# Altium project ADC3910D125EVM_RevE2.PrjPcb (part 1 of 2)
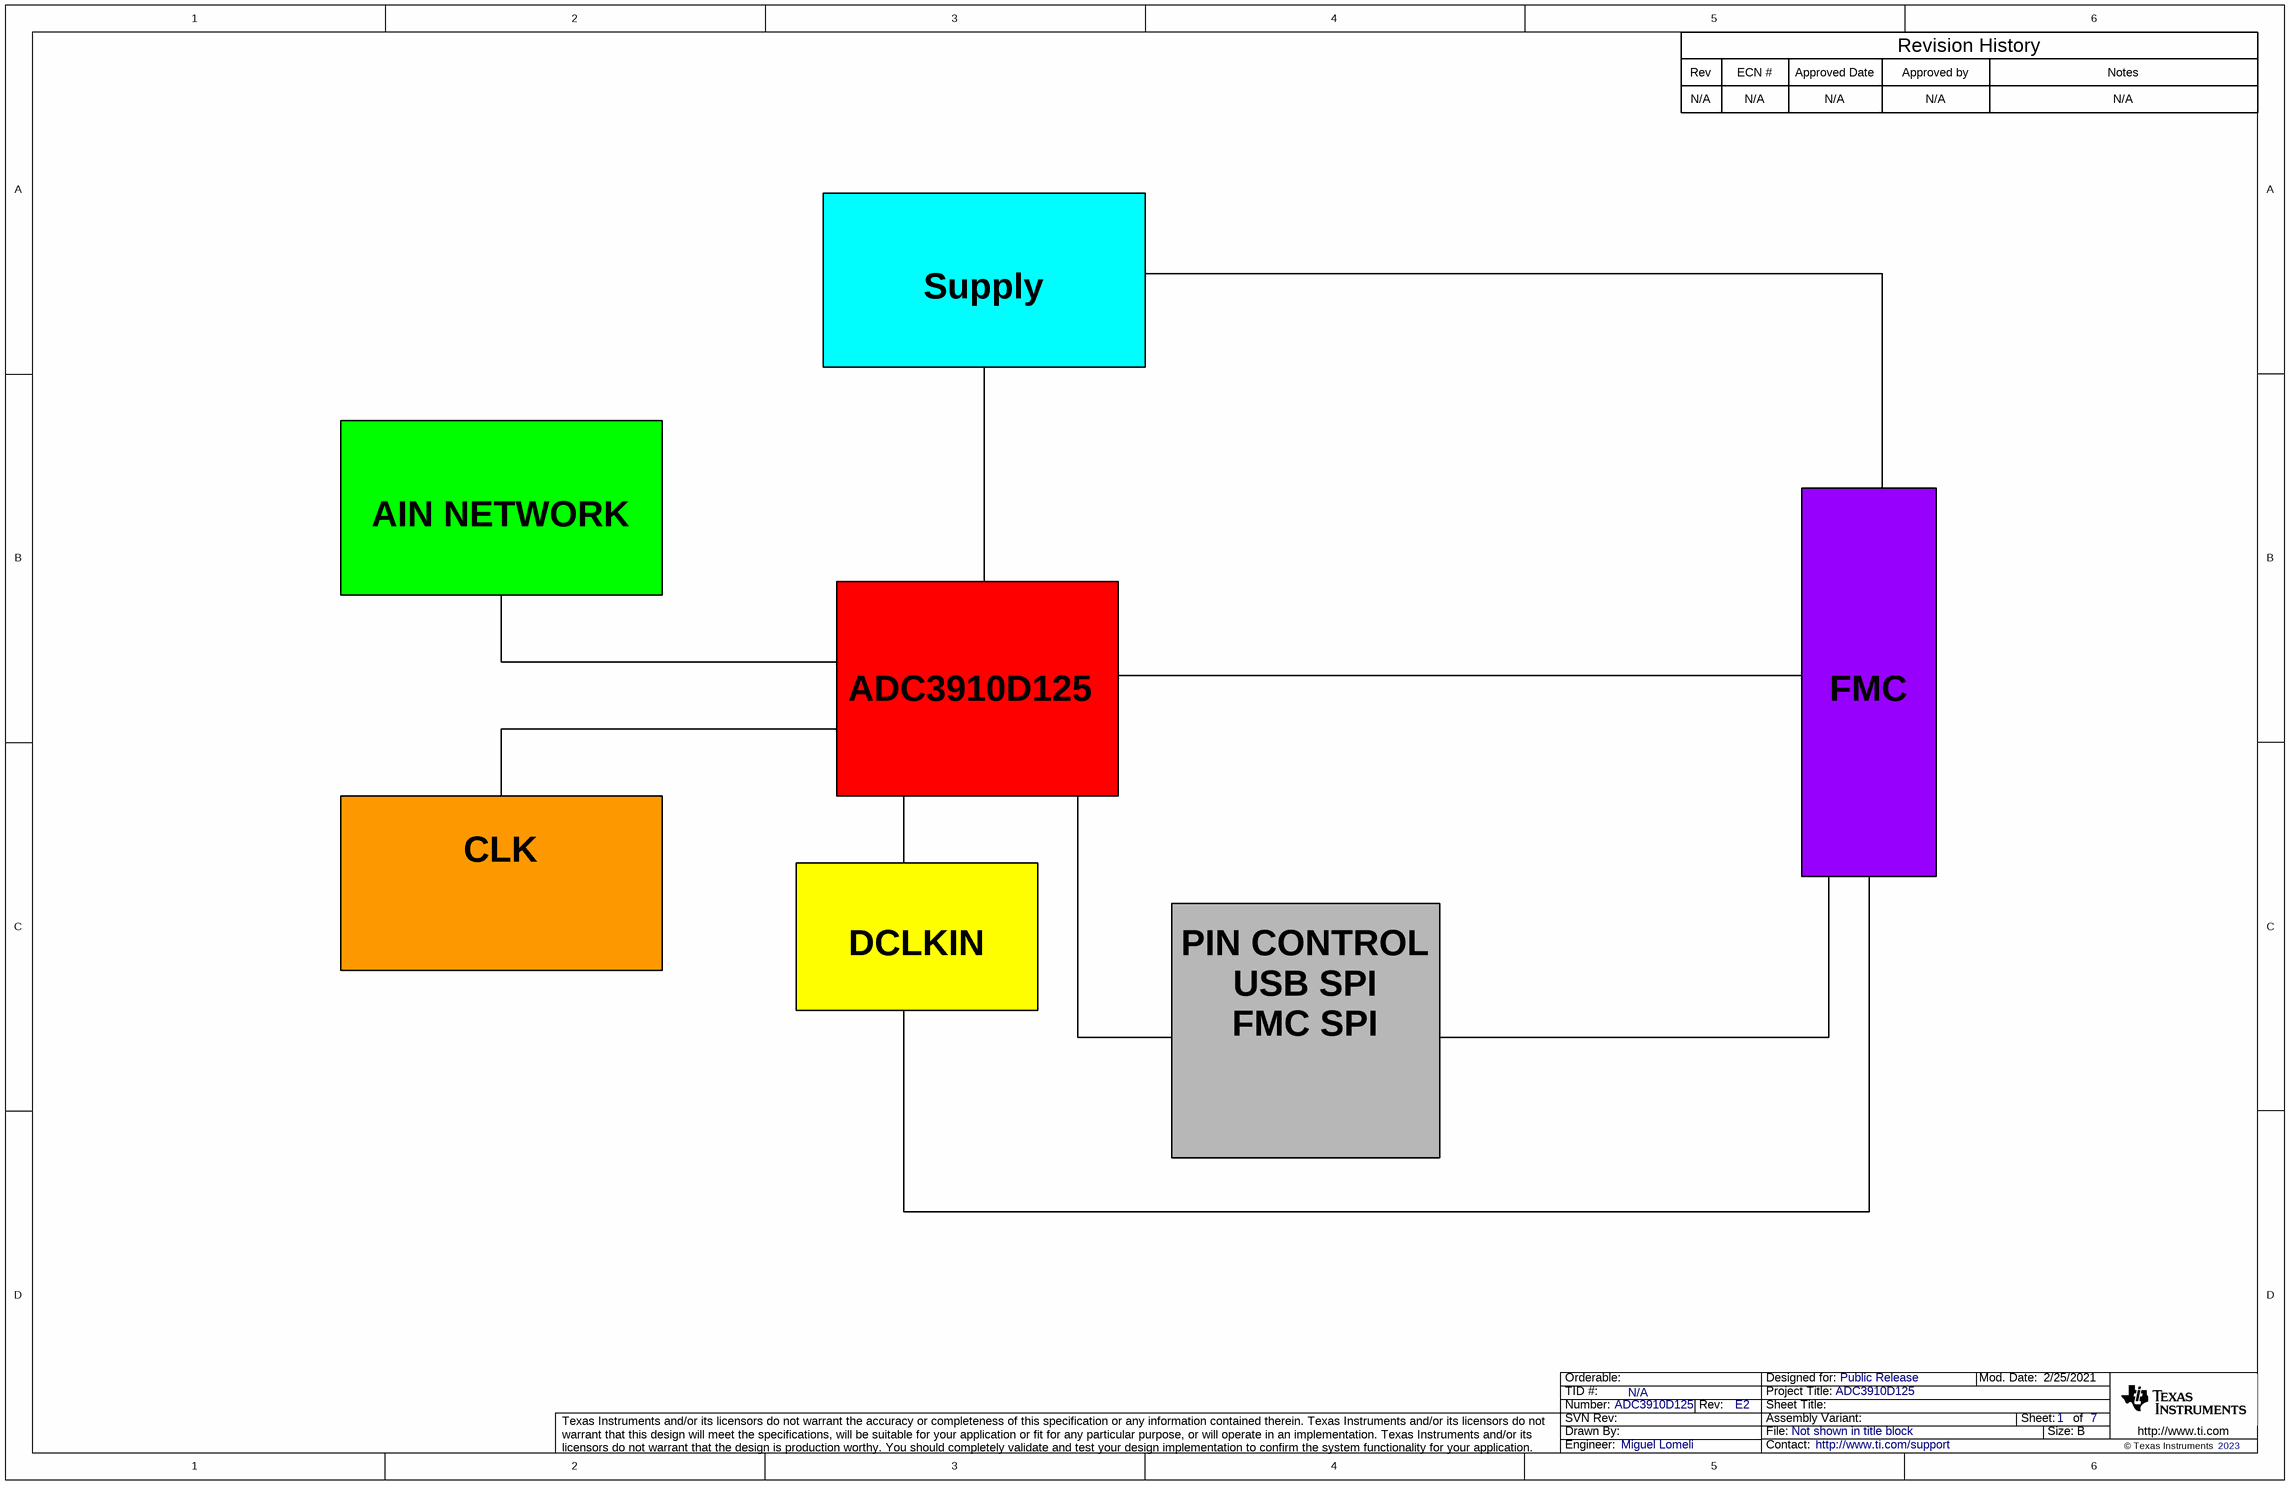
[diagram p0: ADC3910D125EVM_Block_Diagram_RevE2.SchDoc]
CopyrightYear: 2023; PCB_Layout: Miguel Lomeli; PCB_Rev: E2; PRJ_Customer: Public Release; PRJ_Engineer: Miguel Lomeli; PRJ_Number: ADC3910D125; PRJ_Title: ADC3910D125; SCH_Rev: E2; TechSupport: http://www.ti.com/support; TID: N/A
7 sheets, 322 parts. Net scope: flat (ports and power ports of the same name join across sheets).
Board file: ADC3910D125EVM_RevE2.PcbDoc
Sheets:
  ADC3910D125EVM_Block_Diagram_RevE2.SchDoc
  ADC3910D125EVM_Power_RevE2.SchDoc
  ADC3910D125EVM_AIN_CLK_RevE2.SchDoc
  ADC3910D125EVM_DUT_RevE2.SchDoc
  ADC3910D125EVM_USB_Control_RevE2.SchDoc
  ADC3910D125EVM_TSW1418_Header_RevE2.SchDoc
  ADC3910D125EVM_Hardware_RevE2.SchDoc

## Sheet ADC3910D125EVM_Block_Diagram_RevE2.SchDoc
size 431 x 279 mm; Date: Not shown in title block; ApprovedBy: Not shown in title block; CheckedBy: Not shown in title block; Author: Not shown in title block; CompanyName: Not shown in title block; Engineer: Not shown in title block; Organization: Not shown in title block; Address1: Not shown in title block; Address2: Not shown in title block; Address3: Not shown in title block; Address4: Not shown in title block; DocumentNumber: 1; Revision: Use project parameter SCH_Rev; SheetNumber: 1; SheetTotal: 7; PageSetup: Record=PageOptions¦CenterHorizontal=True¦CenterVertical=True¦PrintScale=1.00¦XCorrection=1.00¦YCorrection=1.00¦PrintKind=0¦BorderSize=5000000¦LeftOffset=0¦BottomOffset=0¦Orientation=2¦PaperLength=1000¦PaperWidth=1000¦Scale=100¦PaperSource=15¦PrintQuality=600¦MediaType=1¦DitherType=10¦PaperKind=Letter¦PrintScaleMode=1

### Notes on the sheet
- Rev
- N/A
- ECN #
- Approved Date
- Approved by
- Revision History
- Notes
- Supply
- AIN NETWORK
- ADC3910D125
- FMC
- CLK
- DCLKIN
- PIN CONTROL
- USB SPI
- FMC SPI

## Sheet ADC3910D125EVM_Power_RevE2.SchDoc: Blank Sheet
size 431 x 279 mm; Date: Not shown in title block; ApprovedBy: Not shown in title block; CheckedBy: Not shown in title block; Author: Not shown in title block; CompanyName: Not shown in title block; Engineer: Not shown in title block; Organization: Not shown in title block; Address1: Not shown in title block; Address2: Not shown in title block; Address3: Not shown in title block; Address4: Not shown in title block; DocumentNumber: 5; Revision: Use project parameter SCH_Rev; SheetNumber: 2; SheetTotal: 7; PageSetup: Record=PageOptions¦CenterHorizontal=True¦CenterVertical=True¦PrintScale=1.00¦XCorrection=1.00¦YCorrection=1.00¦PrintKind=0¦BorderSize=5000000¦LeftOffset=0¦BottomOffset=0¦Orientation=2¦PaperLength=1000¦PaperWidth=1000¦Scale=100¦PaperSource=15¦PrintQuality=600¦MediaType=1¦DitherType=10¦PaperKind=Letter¦PrintScaleMode=1
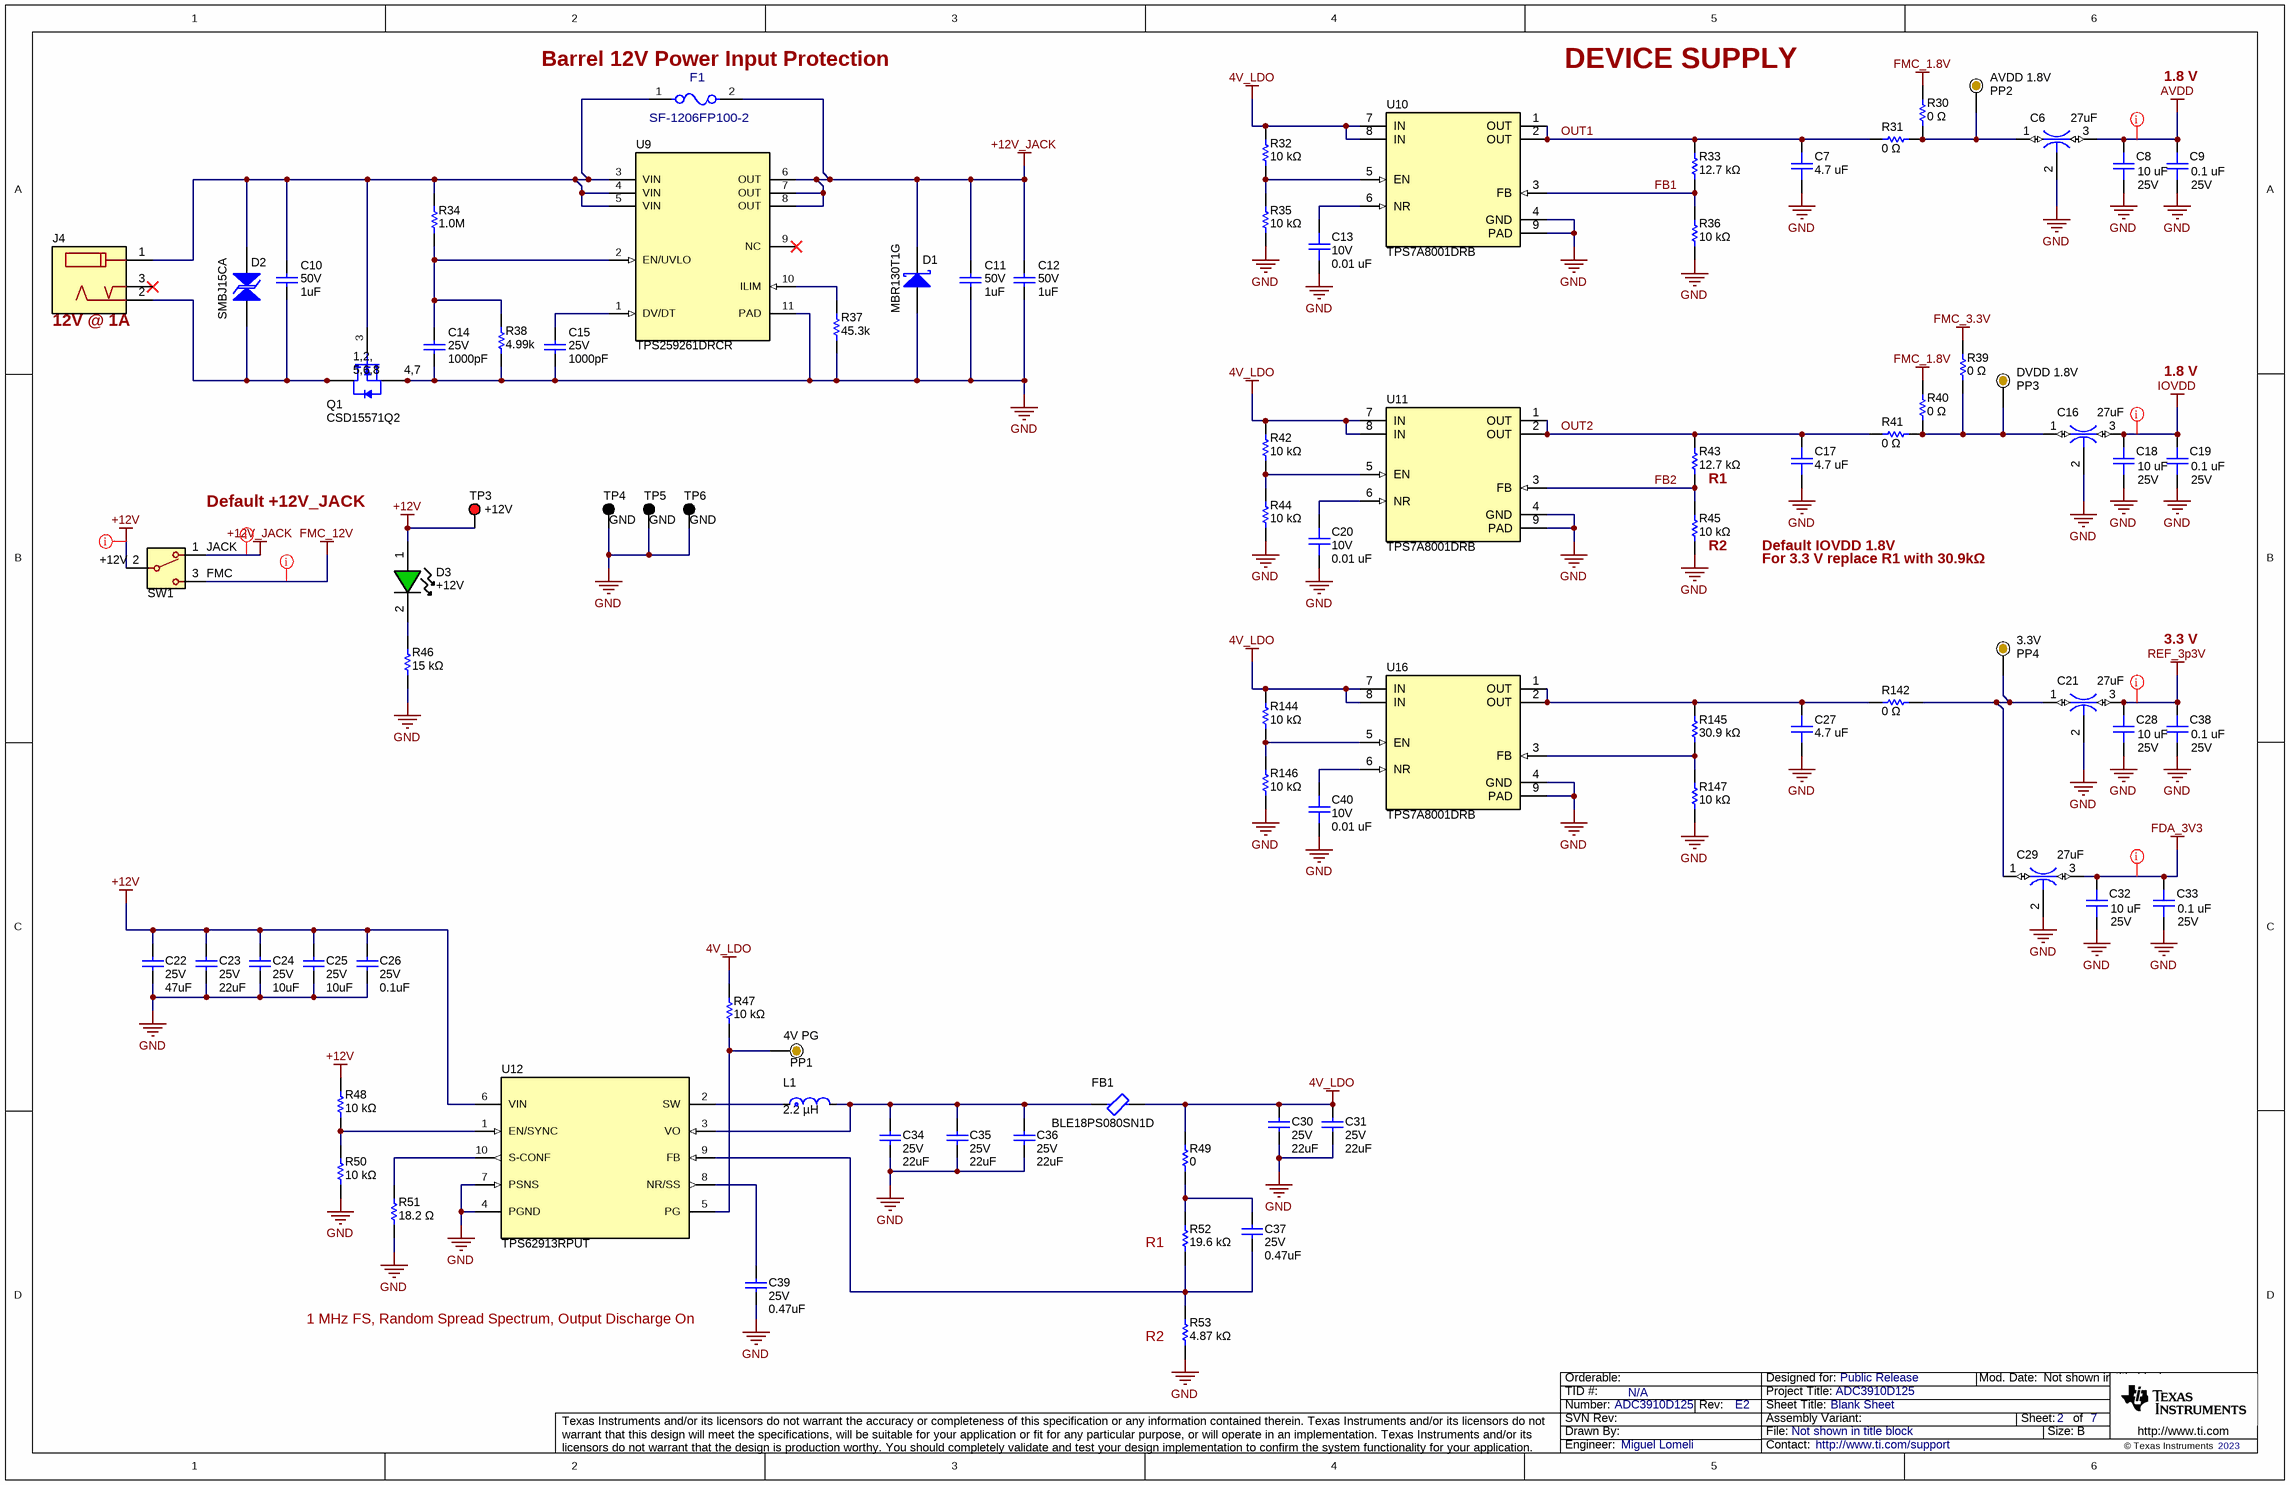
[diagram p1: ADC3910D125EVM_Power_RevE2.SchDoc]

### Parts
C6  value 27uF  [NFM31PC]  (hidden comment: NFM31PC276B0J3L)
C7  value 4.7 uF  [0402L_cap]  (hidden comment: C1005X5R1A475K050BC)
C8  value 10 uF  Voltage - Rated: 25V  [0603L_cap]  (hidden comment: GRM188R61E106KA73J)
C9  value 0.1 uF  Voltage - Rated: 25V  [0402L_cap]  (hidden comment: GRT155R71E104KE01J)
C10  VDC_V: 50V  ValueDisplayed: 1uF  [0805_HV]  (hidden comment: C0805C105K5RACTU)
C11  VDC_V: 50V  ValueDisplayed: 1uF  [0805_HV]  (hidden comment: C0805C105K5RACTU)
C12  VDC_V: 50V  ValueDisplayed: 1uF  [0805_HV]  (hidden comment: C0805C105K5RACTU)
C13  value 0.01 uF  Voltage - Rated: 10V  [0402L_cap]  (hidden comment: 0402ZC103JAT2A)
C14  VDC_V: 25V  ValueDisplayed: 1000pF  [0201_033]  (hidden comment: GRM033R71E102KA01D)
C15  VDC_V: 25V  ValueDisplayed: 1000pF  [0201_033]  (hidden comment: GRM033R71E102KA01D)
C16  value 27uF  [NFM31PC]  (hidden comment: NFM31PC276B0J3L)
C17  value 4.7 uF  [0402L_cap]  (hidden comment: C1005X5R1A475K050BC)
C18  value 10 uF  Voltage - Rated: 25V  [0603L_cap]  (hidden comment: GRM188R61E106KA73J)
C19  value 0.1 uF  Voltage - Rated: 25V  [0402L_cap]  (hidden comment: GRT155R71E104KE01J)
C20  value 0.01 uF  Voltage - Rated: 10V  [0402L_cap]  (hidden comment: 0402ZC103JAT2A)
C21  value 27uF  [NFM31PC]  (hidden comment: NFM31PC276B0J3L)
C22  VDC_V: 25V  ValueDisplayed: 47uF  [1206_190L]  (hidden comment: C3216X5R1E476M160AC)
C23  VDC_V: 25V  ValueDisplayed: 22uF  [0805L]  (hidden comment: GRM21BR61E226ME44L)
C24  VDC_V: 25V  ValueDisplayed: 10uF  [0603L]  (hidden comment: C1608X5R1E106M080AC)
C25  VDC_V: 25V  ValueDisplayed: 10uF  [0603L]  (hidden comment: C1608X5R1E106M080AC)
C26  VDC_V: 25V  ValueDisplayed: 0.1uF  [0201_033]  (hidden comment: GRM033C81E104KE14D)
C27  value 4.7 uF  [0402L_cap]  (hidden comment: C1005X5R1A475K050BC)
C28  value 10 uF  Voltage - Rated: 25V  [0603L_cap]  (hidden comment: GRM188R61E106KA73J)
C29  value 27uF  [NFM31PC]  (hidden comment: NFM31PC276B0J3L)
C30  VDC_V: 25V  ValueDisplayed: 22uF  [0805L]  (hidden comment: GRM21BR61E226ME44L)
C31  VDC_V: 25V  ValueDisplayed: 22uF  [0805L]  (hidden comment: GRM21BR61E226ME44L)
C32  value 10 uF  Voltage - Rated: 25V  [0603L_cap]  (hidden comment: GRM188R61E106KA73J)
C33  value 0.1 uF  Voltage - Rated: 25V  [0402L_cap]  (hidden comment: GRT155R71E104KE01J)
C34  VDC_V: 25V  ValueDisplayed: 22uF  [0805L]  (hidden comment: GRM21BR61E226ME44L)
C35  VDC_V: 25V  ValueDisplayed: 22uF  [0805L]  (hidden comment: GRM21BR61E226ME44L)
C36  VDC_V: 25V  ValueDisplayed: 22uF  [0805L]  (hidden comment: GRM21BR61E226ME44L)
C37  VDC_V: 25V  ValueDisplayed: 0.47uF  [0402L]  (hidden comment: GRM155R61E474KE01D)
C38  value 0.1 uF  Voltage - Rated: 25V  [0402L_cap]  (hidden comment: GRT155R71E104KE01J)
C39  VDC_V: 25V  ValueDisplayed: 0.47uF  [0402L]  (hidden comment: GRM155R61E474KE01D)
C40  value 0.01 uF  Voltage - Rated: 10V  [0402L_cap]  (hidden comment: 0402ZC103JAT2A)
D1  MBR130T1G  [SOD-123]
D2  SMBJ15CA  [SMB-Bi]
D3  Text1: +12V  [LED_LTST-C190-Green]  (hidden comment: LTST-C191TGKT)
F1  SF-1206FP100-2  [FP-SF-1206FP100-2_1206-MFG]
FB1  BLE18PS080SN1D  [0603L]
J4  Text1: 12V @ 1A  [RAPC722X]  (hidden comment: RAPC722X)
L1  value 2.2 µH  [XGL5030]  (hidden comment: XGL5030-222MEC)
PP1  Text1: 4V PG  [ProbePoint_TH_40mil]  (hidden comment: Probe Point)  (no BOM)
PP2  Text1: AVDD 1.8V  [ProbePoint_TH_40mil]  (hidden comment: Probe Point)  (no BOM)
PP3  Text1: DVDD 1.8V  [ProbePoint_TH_40mil]  (hidden comment: Probe Point)  (no BOM)
PP4  Text1: 3.3V  [ProbePoint_TH_40mil]  (hidden comment: Probe Point)  (no BOM)
Q1  CSD15571Q2  [DQK0006C]
R30  value 0 Ω  [0603L]  (hidden comment: ERJ-U030R00V)
R31  value 0 Ω  [0603L]  (hidden comment: ERJ-U030R00V)
R32  value 10 kΩ  [0402L]  (hidden comment: ERJ-2RKF1002X)
R33  value 12.7 kΩ  [0402L]  (hidden comment: ERJ-2RKF1272X)
R34  ValueDisplayed: 1.0M  [0201]  (hidden comment: RC0201JR-071ML)
R35  value 10 kΩ  [0402L]  (hidden comment: ERJ-2RKF1002X)
R36  value 10 kΩ  [0402L]  (hidden comment: ERJ-2RKF1002X)
R37  ValueDisplayed: 45.3k  [0201]  (hidden comment: RC0201FR-7D45K3L)
R38  ValueDisplayed: 4.99k  [0201]  (hidden comment: RC0201FS-7D4K99L)
R39  value 0 Ω  [0603L]  (hidden comment: ERJ-U030R00V)
R40  value 0 Ω  [0603L]  (hidden comment: ERJ-U030R00V)
R41  value 0 Ω  [0603L]  (hidden comment: ERJ-U030R00V)
R42  value 10 kΩ  [0402L]  (hidden comment: ERJ-2RKF1002X)
R43  value 12.7 kΩ  [0402L]  (hidden comment: ERJ-2RKF1272X)
R44  value 10 kΩ  [0402L]  (hidden comment: ERJ-2RKF1002X)
R45  value 10 kΩ  [0402L]  (hidden comment: ERJ-2RKF1002X)
R46  value 15 kΩ  [0603L]  (hidden comment: ERJ-UP3F1502V)
R47  value 10 kΩ  [0402L]  (hidden comment: ERJ-2RKF1002X)
R48  value 10 kΩ  [0402L]  (hidden comment: ERJ-2RKF1002X)
R49  ValueDisplayed: 0  [0402L]  (hidden comment: ERJ-2GE0R00X)
R50  value 10 kΩ  [0402L]  (hidden comment: ERJ-2RKF1002X)
R51  value 18.2 Ω  [0402L]  (hidden comment: ERJ-2RKF18R2X)
R52  value 19.6 kΩ  [0402L]  (hidden comment: ERJ-2RKF1962X)
R53  value 4.87 kΩ  [0402L]  (hidden comment: ERJ-2RKF4871X)
R142  value 0 Ω  [0603L]  (hidden comment: ERJ-U030R00V)
R144  value 10 kΩ  [0402L]  (hidden comment: ERJ-2RKF1002X)
R145  value 30.9 kΩ  [0402L]  (hidden comment: ERJ-2RKF3092X)
R146  value 10 kΩ  [0402L]  (hidden comment: ERJ-2RKF1002X)
R147  value 10 kΩ  [0402L]  (hidden comment: ERJ-2RKF1002X)
SW1  Text1: JACK  Text2: +12V  Text3: FMC  [FP-1101M2S3CGE2_SIP3-MFG]  (hidden comment: 1101M2S3CGE2)
TP3  Text1: +12V  [Keystone5000]  (hidden comment: 5000)
TP4  Text1: GND  [Keystone5011]  (hidden comment: 5011)
TP5  Text1: GND  [Keystone5011]  (hidden comment: 5011)
TP6  Text1: GND  [Keystone5011]  (hidden comment: 5011)
U9  TPS259261DRCR  [DRC0010J]
U10  TPS7A8001DRB  [DRB0008A]
U11  TPS7A8001DRB  [DRB0008A]
U12  TPS62913RPUT  [RPU0010A]
U16  TPS7A8001DRB  [DRB0008A]

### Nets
4V_LDO: C30.1 C31.1 FB1.2 R32.2 R42.2 R47.2 R49.2 R144.2 U10.7(IN) U10.8(IN) U11.7(IN) U11.8(IN) U16.7(IN) U16.8(IN)
+12V: C22.1 C23.1 C24.1 C25.1 C26.1 D3.1(A) R48.2 SW1.2(COMM) TP3.1 U12.6(VIN)
+12V_JACK: C11.1 C12.1 D1.1(K) F1.2 SW1.1 U9.6(OUT) U9.7(OUT) U9.8(OUT)
AVDD: C6.3 C8.2 C9.2
FDA_3V3: C29.3 C32.2 C33.2
FMC_1.8V: R30.2 R40.1
FMC_3.3V: R39.2
FMC_12V: SW1.3
GND: C6.2 C7.1 C8.1 C9.1 C11.2 C12.2 C13.1 C14.2 C15.2 C16.2 C17.1 C18.1 C19.1 C20.1 C21.2 C22.2 C23.2 C24.2 C25.2 C26.2 C27.1 C28.1 C29.2 C30.2 C31.2 C32.1 C33.1 C34.2 C35.2 C36.2 C38.1 C39.2 C40.1 D1.2(A) Q1.4(S) Q1.7(S) R35.1 R36.1 R37.1 R38.2 R44.1 R45.1 R46.1 R50.1 R51.1 R53.1 R146.1 R147.1 TP4.1 TP5.1 TP6.1 U9.11(PAD) U10.4(GND) U10.9(PAD) U11.4(GND) U11.9(PAD) U12.4(PGND) U12.7(PSNS) U16.4(GND) U16.9(PAD)
IOVDD: C16.3 C18.2 C19.2
REF_3p3V: C21.3 C28.2 C38.2
FB1: R33.1 R36.2 U10.3(FB)
FB2: R43.1 R45.2 U11.3(FB)
OUT1: C7.2 R31.2 R33.2 U10.1(OUT) U10.2(OUT)
OUT2: C17.2 R41.2 R43.2 U11.1(OUT) U11.2(OUT)
NetC6_1: C6.1 PP2.1 R30.1 R31.1
NetC10_1: C10.1 D2.2 F1.1 J4.1 Q1.3(G) R34.2 U9.3(VIN) U9.4(VIN) U9.5(VIN)
NetC10_2: C10.2 D2.1 J4.2 Q1.1(D) Q1.2(D) Q1.5(D) Q1.6(D) Q1.8(D)
NetC13_2: C13.2 U10.6(NR)
NetC14_1: C14.1 R34.1 R38.1 U9.2(EN/UVLO)
NetC15_1: C15.1 U9.1(DV/DT)
NetC16_1: C16.1 PP3.1 R39.1 R40.2 R41.1
NetC20_2: C20.2 U11.6(NR)
NetC21_1: C21.1 C29.1 PP4.1 R142.1
NetC27_2: C27.2 R142.2 R145.2 U16.1(OUT) U16.2(OUT)
NetC34_1: C34.1 C35.1 C36.1 FB1.1 L1.2 U12.3(VO)
NetC37_1: C37.1 R49.1 R52.2
NetC37_2: C37.2 R52.1 R53.2 U12.9(FB)
NetC39_1: C39.1 U12.8(NR/SS)
NetC40_2: C40.2 U16.6(NR)
NetD3_2: D3.2(K) R46.2
NetL1_1: L1.1 U12.2(SW)
NetPP1_1: PP1.1 R47.1 U12.5(PG)
NetR32_1: R32.1 R35.2 U10.5(EN)
NetR37_2: R37.2 U9.10(ILIM)
NetR42_1: R42.1 R44.2 U11.5(EN)
NetR48_1: R48.1 R50.2 U12.1(EN/SYNC)
NetR51_2: R51.2 U12.10(S-CONF)
NetR144_1: R144.1 R146.2 U16.5(EN)
NetR145_1: R145.1 R147.2 U16.3(FB)

Not connected (* = marked no-connect by the designer): J4 3*; U9 9(NC)*

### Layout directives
net class Power: +12V, +12V_JACK, AVDD, FDA_3V3, FMC_12V, IOVDD, REF_3p3V

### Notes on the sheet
- (near F1) Barrel 12V Power Input Protection
- DEVICE SUPPLY
- 1.8 V
- Default +12V_JACK
- (near R43) R1
- (near R45) R2
- Default IOVDD 1.8V
- For 3.3 V replace R1 with 30.9kΩ
- 3.3 V
- (near R52) R1
- 1 MHz FS, Random Spread Spectrum, Output Discharge On
- (near R53) R2

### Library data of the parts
C6 C16 C21 C29 = dcp00001: Feed through capactior 27uF; Manufacturer: Murata; CompType: Feed Thru Cap; Tolerance: ±20%; Voltage - Rated: 6.3V; Current: 6A; DCR: 5 mΩ; SizeX_mm: 3.2; SizeY_mm: 1.6; SizeZ_mm: 1.5
C7 C17 C27 = capcc03298: CAP CER 4.7UF 10V X5R 0402; Manufacturer: TDK Corporation; Tolerance: ±10%; SizeX_mm: 1; SizeY_mm: 0.5; SizeZ_mm: 0.65; CompType: Capacitor Ceramic
C8 C18 C28 C32 = capcc09400: CAP CER 10UF 25V X5R 0603; Manufacturer: Murata; SizeZ_mm: 1; SizeX_mm: 1.6; SizeY_mm: 0.8; CompType: Capacitor Ceramic; Tolerance: ±10%
C9 C19 C33 C38 = capcc09401: CAP CER 0.1UF 25V X7R 0402; Manufacturer: Murata; SizeZ_mm: 0.7; SizeX_mm: 1; SizeY_mm: 0.5; CompType: Capacitor Ceramic; Tolerance: ±10%
C10-C12 = CMP-0007730-2: CAP, CERM, 1 uF, 50 V, +/- 10%, X7R, 0805; Manufacturer: Kemet; TaMin_C: -55°C; Polarized: N; SizeAreaWB_mm2: 6.75; Value1: Unknown; U/M: EA; Value: 1uF; TaMax_C: 125°C; SizeZ_mm: 1.45; SizeX_mm: 2; SizeY_mm: 1.25; Cap_Case: 0805; SizeArea_mm2: 2.5; Cap_F: 1µF; AEC Category: Q200
C13 C20 C40 = capcc05563: CAP CER 10000PF 10V X7R 0402; Manufacturer: KYOCERA AVX; CompType: Capacitor Ceramic; Tolerance: ±5%; SizeX_mm: 1; SizeY_mm: 0.5; SizeZ_mm: 0.56
C14 C15 = CMP-0009764-1: CAP, CERM, 1000 pF, 25 V, +/- 10%, X7R, 0201; Manufacturer: MuRata; TaMin_C: -55°C; Polarized: N; SizeAreaWB_mm2: 2.08; Value1: Unknown; U/M: EA; Value: 1000pF; TaMax_C: 125°C; SizeZ_mm: 0.33; SizeX_mm: 0.6; SizeY_mm: 0.3; Cap_Case: 0201; SizeArea_mm2: 0.18; Cap_F: 1nF; AEC Category: Q200
C22 = CMP-0008656-2: CAP, CERM, 47 uF, 25 V, +/- 20%, X5R, 1206_190; Manufacturer: TDK; TaMin_C: -55°C; Polarized: N; SizeAreaWB_mm2: 10.92; Value1: Unknown; U/M: EA; Value: 47uF; TaMax_C: 85°C; SizeZ_mm: 1.9; SizeX_mm: 3.2; SizeY_mm: 1.6; Cap_Case: 1206; SizeArea_mm2: 5.12; Cap_F: 47µF; AEC Category: Q200
C23 C30 C31 C34-C36 = CMP-0008305-2: CAP, CERM, 22 uF, 25 V, +/- 20%, X5R, 0805; Manufacturer: MuRata; TaMin_C: -55°C; Polarized: N; SizeAreaWB_mm2: 6.75; Value1: Unknown; U/M: EA; Value: 22uF; TaMax_C: 85°C; SizeZ_mm: 1.45; SizeX_mm: 2; SizeY_mm: 1.25; Cap_Case: 0805; SizeArea_mm2: 2.5; Cap_F: 22µF; AEC Category: Q200
C24 C25 = CMP-0007007-5: CAP, CERM, 10 uF, 25 V, +/- 20%, X5R, 0603; Manufacturer: TDK; TaMin_C: -55°C; ESR_ohm: 4.639m; Polarized: N; SizeAreaWB_mm2: 4.68; Value1: 0.004639 ohm; U/M: EA; Value: 10uF; TaMax_C: 85°C; SizeZ_mm: 1; SizeX_mm: 1.6; SizeY_mm: 0.8; Cap_Case: 0603; SizeArea_mm2: 1.28; Cap_F: 10µF; IRMS_A: 2.4141A; AEC Category: Q200
C26 = CMP-0009688-3: CAP, CERM, 0.1 uF, 25 V, +/- 10%, X6S, 0201; Manufacturer: MuRata; TaMin_C: -55°C; Polarized: N; SizeAreaWB_mm2: 2.08; Value1: Unknown; U/M: EA; Value: 0.1uF; TaMax_C: 105°C; SizeZ_mm: 0.33; SizeX_mm: 0.6; SizeY_mm: 0.3; Cap_Case: 0201; SizeArea_mm2: 0.18; Cap_F: 100nF; AEC Category: Q200
C37 C39 = CMP-0064928-2: CAP, CERM, 0.47 uF, 25 V,+/- 10%, X5R, 0402; Manufacturer: MuRata; TaMin_C: -55°C; Polarized: N; SizeAreaWB_mm2: 3; Value1: Unknown; U/M: EA; Value: 0.47uF; TaMax_C: 85°C; SizeZ_mm: 0.6; SizeX_mm: 1; SizeY_mm: 0.5; Cap_Case: 0402; Cap_F: 470nF; AEC Category: Q200
D1 = CMP-0028547-2: Diode, Schottky, 30 V, 1 A, SOD-123; Manufacturer: ON Semiconductor; Io_A: 1A; Green_Lifecycle: Active; SizeAreaWB_mm2: 13.095; Vr_V: 30V; Green_REACh: Passed; TJmax_C: 125°C; Value: 30V; SizeZ_mm: 1.35; SizeX_mm: 3.85; SizeY_mm: 1.7; Vf_V: 470mV; Value2: 0.47V; SizeArea_mm2: 6.545; AEC Category: Q101; RJC_CperW: 108
D2 = CMP-0006044-3: Diode, TVS, Bi, 15 V, 24.4 Vc, SMB; Manufacturer: Fairchild Semiconductor; Value1: 600W; Value: 15V; AEC Category: Q101; Ppk: 15kW
D3 = cmp00247: LED GREEN CLEAR CHIP SMD; Manufacturer: Lite-On Inc.; Current Rating (Amps): 20mA; Voltage - Forward (Vf) (Typ): 3.2V; SizeX_mm: 1.6; SizeY_mm: 0.8; SizeZ_mm: 0.65
F1 = CMP-0095990-1: 1 A AC 63 V DC Fuse Board Mount (Cartridge Style Excluded) Surface Mount 1206 (3216 Metric); Manufacturer: Bourns; SizeZ_mm: 0.7mm; MeltingTyp: 0.062A2Sec; Fuse Speed: Fast; Res_ohm: 0.1455Ω; Fuse Interrupt Dc Current: 50A; AEC Qualified: No; Fuse Current: 1A
FB1 = dcp00379: FERRITE BEAD; Manufacturer: Murata Electronics; Current: 8A; Impedance: 8.5 Ω; DCR: 4 mΩ
J4 = cmp00022: Power Jack, mini, 2.1mm OD, R/A, TH; Manufacturer: Switchcraft
L1 = LSMT56800038: POWER INDUCTOR, SHIELDED, COMPOS; Manufacturer: COILCRAFT; Current Rating (Amps): 12.9 A; Current - Saturation (Isat): 9.4A; DC Resistance (DCR): 10.6m Ω; Inductance Frequency - Test: 1 MHz; Frequency - Self Resonant: 34MHz; SizeX_mm: 5.68; SizeY_mm: 5.48; SizeZ_mm: 3.1
PP1-PP4 = cmp00025: Probe Point that can be used in lue of a test point
Q1 = CMP-0000207-1: MOSFET, N-CH, 20 V, 10 A, DQK0006C (WSON-6); Alternate Manufacturer: None; Manufacturer: Texas Instruments; SizeZ_mm: 0.8; ChType: N; Value2: 2.5 nC; Value1: 19; VdsMax_V: 20V; SizeX_mm: 2; Value: 20V; Rdson45_ohm: 19.2; SizeArea_mm2: 4; AEC Category: Q101; IdsMax_A: 10A; SizeAreaWB_mm2: 9; U/M: EA; QgTyp_nC: 2.5
R30 R31 R39-R41 R142 = RSMD060312253: RES 0 OHM JUMPER 0603 SMD; Manufacturer: Panasonic Electronic Components; Power (Watts): 0.1W, 1/10W; Temperature Coefficient: ±200ppm/°C; SizeX_mm: 1.6; SizeY_mm: 0.8; SizeZ_mm: 0.55; CompType: Resistor SMD
R32 R35 R36 R42 R44 R45 R47 R48 R50 R144 R146 R147 = RSMD040200314: RES SMD 10K OHM 1% 1/10W 0402; Manufacturer: Panasonic Electronic Components; Power (Watts): 0.1W, 1/10W; Temperature Coefficient: ±100ppm/°C; SizeX_mm: 1; SizeY_mm: 0.5; SizeZ_mm: 0.4; CompType: Resistor SMD
R33 R43 = RSMD040202026: RES SMD 12.7K OHM 1% 1/10W 0402; Manufacturer: Panasonic Electronic Components; Power (Watts): 0.1W, 1/10W; Temperature Coefficient: ±100ppm/°C; SizeX_mm: 1; SizeY_mm: 0.5; SizeZ_mm: 0.4
R34 = CMP-0027059-1: RES, 1.0 M, 5%, 0.05 W, 0201; Manufacturer: Yageo America; Power_W: 50mW; TempCo: 200 ppm/C; Value_Code: 1M00; U/M: EA; Value: 1.0Meg; EIA_Code: E24; Res_ohm: 1M; SizeX_mm: 0.6; SizeY_mm: 0.3; SizeZ_mm: 0.26; Value2: 0.05W; SizeArea_mm2: 0.18; AEC Qualified: N; VDC_V: 25V; AEC Category: Q200
R37 = CMP-0028019-1: RES, 45.3 k, 1%, 0.05 W, 0201; Manufacturer: Yageo America; Power_W: 50mW; TempCo: 200 ppm/C; Value_Code: 45k3; U/M: EA; Value: 45.3k; EIA_Code: E96; SizeX_mm: 0.6; SizeY_mm: 0.3; SizeZ_mm: 0.26; Value2: 0.05W; SizeArea_mm2: 0.18; AEC Qualified: N; VDC_V: 25V; AEC Category: Q200
R38 = CMP-0028107-1: RES, 4.99 k, 1%, 0.05 W, 0201; Manufacturer: Yageo America; Power_W: 50mW; TempCo: 200 ppm/C; Value_Code: 4k99; U/M: EA; Value: 4.99k; EIA_Code: E96; SizeX_mm: 0.6; SizeY_mm: 0.3; SizeZ_mm: 0.26; Value2: 0.05W; SizeArea_mm2: 0.18; AEC Qualified: N; VDC_V: 25V; AEC Category: Q200
R46 = RSMD060304038: RES 15K OHM 1% 1/4W 0603; Manufacturer: Panasonic Electronic Components; CompType: Resistor SMD; Power (Watts): 0.25W, 1/4W; Temperature Coefficient: ±100ppm/°C; SizeX_mm: 1.6; SizeY_mm: 0.8; SizeZ_mm: 0.55
R49 = CMP-0026992-3: RES, 0, 5%, 0.1 W, AEC-Q200 Grade 0, 0402; Manufacturer: Panasonic; Power_W: 100mW; TempCo: 600 ppm/C; Value_Code: 0000; Value: 0; EIA_Code: E24; SizeX_mm: 1; SizeY_mm: 0.5; SizeZ_mm: 0.6; Value2: 0.1W; AEC Qualified: Y; VDC_V: 50V; AEC Category: Q200; SizeAreaWB_mm2: 3
R51 = RSMD040200251: RES SMD 18.2 OHM 1% 1/10W 0402; Manufacturer: Panasonic Electronic Components; Power (Watts): 0.1W, 1/10W; Temperature Coefficient: ±100ppm/°C; SizeX_mm: 1; SizeY_mm: 0.5; SizeZ_mm: 0.4
R52 = RSMD040201128: RES SMD 19.6K OHM 1% 1/10W 0402; Manufacturer: Panasonic Electronic Components; CompType: Resistor SMD; Power (Watts): 0.1W, 1/10W; Temperature Coefficient: ±100ppm/°C; SizeX_mm: 1; SizeY_mm: 0.5; SizeZ_mm: 0.4
R53 = RSMD040201711: RES SMD 4.87K OHM 1% 1/10W 0402; Manufacturer: Panasonic Electronic Components; Power (Watts): 0.1W, 1/10W; Temperature Coefficient: ±100ppm/°C; SizeX_mm: 1; SizeY_mm: 0.5; SizeZ_mm: 0.4
R145 = RSMD040202088: RES SMD 30.9K OHM 1% 1/10W 0402; Manufacturer: Panasonic Electronic Components; CompType: Resistor SMD; Power (Watts): 0.1W, 1/10W; Temperature Coefficient: ±100ppm/°C; SizeX_mm: 1; SizeY_mm: 0.5; SizeZ_mm: 0.4
SW1 = cmp00021: Switch Slide SPDT 120V, 6A; Manufacturer: C&K Components
TP3 = connector00030: Test Point, Miniature, Red, TH; Manufacturer: Keystone
TP4-TP6 = cmp00041: Test Point, Multipurpose, Black, TH; Manufacturer: Keystone
U9 = CMP-0074225-5: 12V, 5A, 30mΩ eFuse with Adjustable +/-15% Accurate Current Limit, DRC0010J (VSON-10); Alternate PartNumber: TPS259261DRCT; Alternate Manufacturer: Texas Instruments; Green_Lifecycle: Active; SizeAreaWB_mm2: 16; Green_REACh: Passed; SizeZ_mm: 1; SizeX_mm: 3; SizeArea_mm2: 9; CompType: IC; AEC Category: Q200; AEC Qualified: N; Rating: Catalog
U10 U11 U16 = cmp00168: 1-A, high-PSRR, ultra-low-dropout voltage regulator with low-IQ & enable; Manufacturer: Texas Instruments; CompType: LDO
U12 = CMP-0860321-2: 3A Low Noise and Low Ripple buck converter, RPU0010A (VQFN-10); Alternate Manufacturer: Texas Instruments; SizeArea_mm2: 4; SizeAreaWB_mm2: 9; AEC Category: Q200; SizeY_mm: 2; CompType: IC; SizeZ_mm: 1; AEC Qualified: N

## Sheet ADC3910D125EVM_AIN_CLK_RevE2.SchDoc
size A2; Date: Not shown in title block; ApprovedBy: Not shown in title block; CheckedBy: Not shown in title block; Author: Not shown in title block; CompanyName: Not shown in title block; Engineer: Not shown in title block; Organization: Not shown in title block; Address1: Not shown in title block; Address2: Not shown in title block; Address3: Not shown in title block; Address4: Not shown in title block; DocumentNumber: 1; Revision: Use project parameter SCH_Rev; SheetNumber: 3; SheetTotal: 7; PageSetup: Record=PageOptions¦CenterHorizontal=True¦CenterVertical=True¦PrintScale=0.69¦XCorrection=1.00¦YCorrection=1.00¦PrintKind=0¦BorderSize=5000000¦LeftOffset=0¦BottomOffset=0¦Orientation=2¦PaperLength=1000¦PaperWidth=1000¦Scale=100¦PaperSource=15¦PrintQuality=600¦MediaType=1¦DitherType=10¦PaperKind=Letter¦PrintScaleMode=1
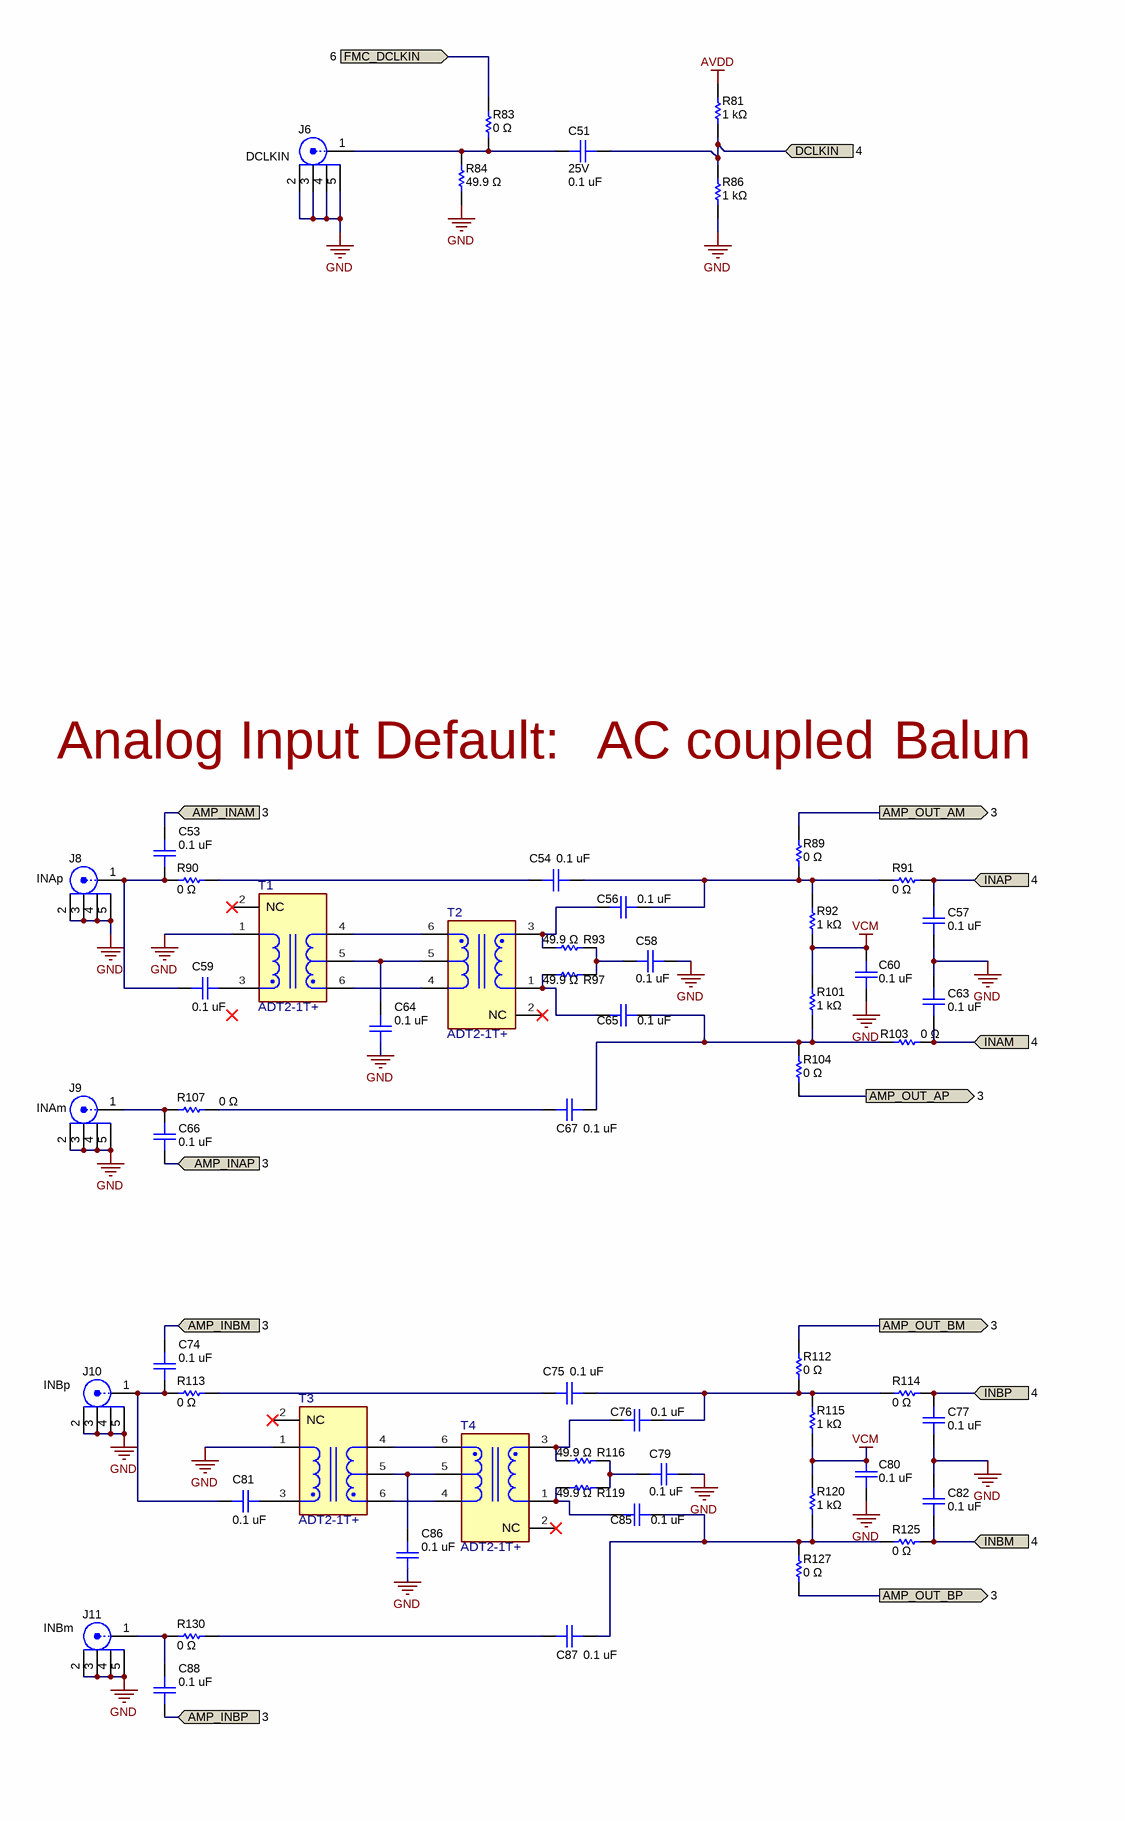
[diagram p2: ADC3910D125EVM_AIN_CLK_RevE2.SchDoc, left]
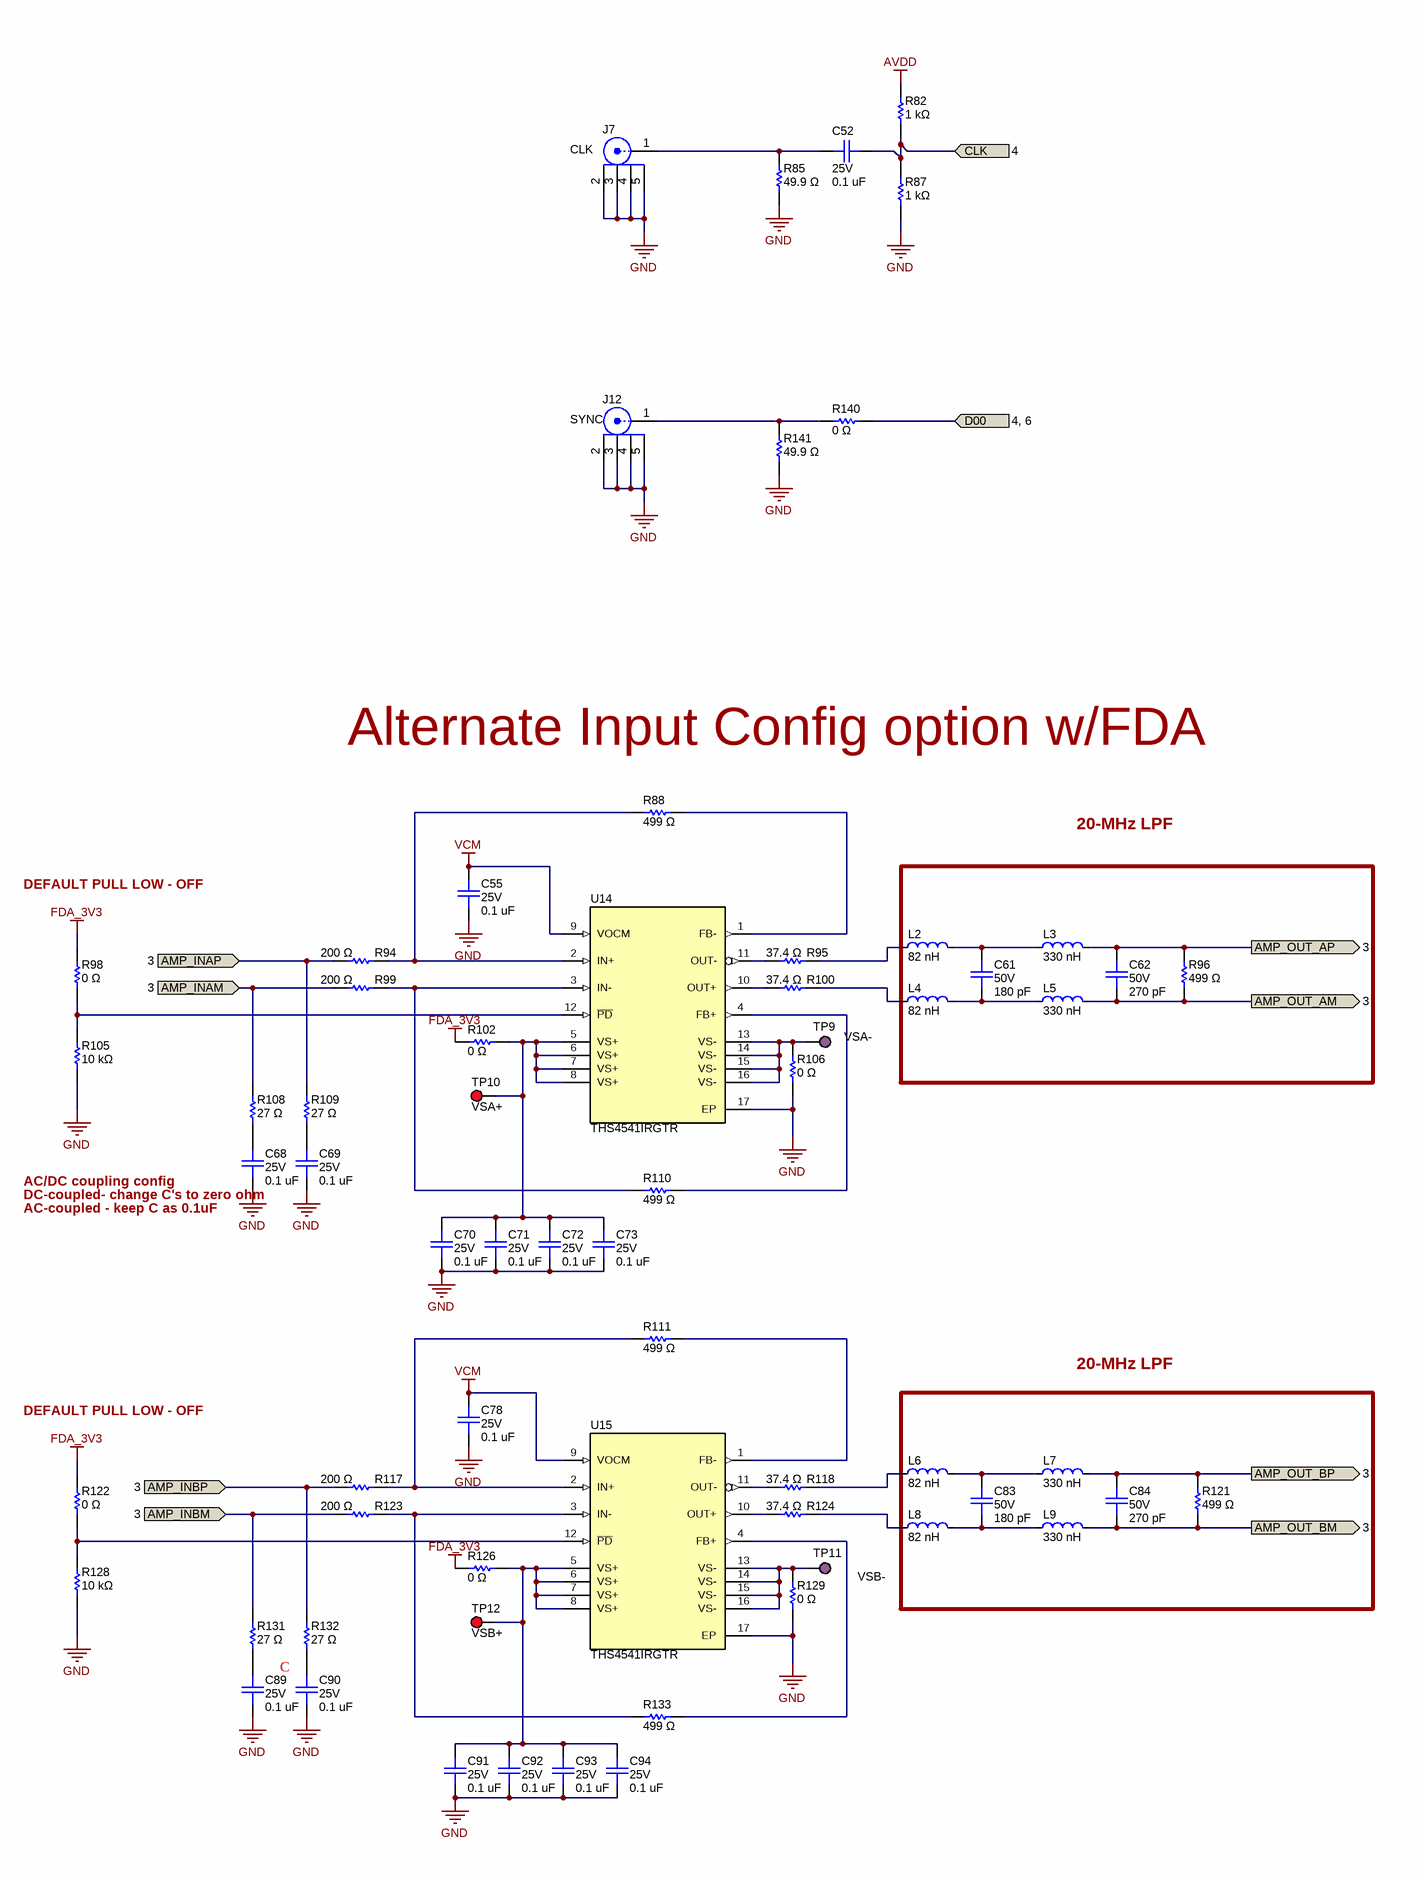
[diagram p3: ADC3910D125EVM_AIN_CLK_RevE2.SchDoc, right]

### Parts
C51  value 0.1 uF  Voltage - Rated: 25V  [0402L_cap]  (hidden comment: GRT155R71E104KE01J)
C52  value 0.1 uF  Voltage - Rated: 25V  [0402L_cap]  (hidden comment: GRT155R71E104KE01J)
C53  value 0.1 uF  [0402L_cap]  (hidden comment: 0402YC104JAT4A)
C54  value 0.1 uF  [0402L_cap]  (hidden comment: 0402YC104JAT4A)
C55  value 0.1 uF  Voltage - Rated: 25V  [0402L_cap]  (hidden comment: GRT155R71E104KE01J)
C56  value 0.1 uF  [0402L_cap]  (hidden comment: 0402YC104JAT4A)
C57  value 0.1 uF  [0402L_cap]  (hidden comment: 0402YC104JAT4A)
C58  value 0.1 uF  [0402L_cap]  (hidden comment: 0402YC104JAT4A)
C59  value 0.1 uF  [0402L_cap]  (hidden comment: 0402YC104JAT4A)
C60  value 0.1 uF  [0402L_cap]  (hidden comment: 0402YC104JAT4A)
C61  value 180 pF  Voltage - Rated: 50V  [0402L_cap]  (hidden comment: 04025C181KAT2A)
C62  value 270 pF  Voltage - Rated: 50V  [0402L_cap]  (hidden comment: 04025C271JAT2A)
C63  value 0.1 uF  [0402L_cap]  (hidden comment: 0402YC104JAT4A)
C64  value 0.1 uF  [0402L_cap]  (hidden comment: 0402YC104JAT4A)
C65  value 0.1 uF  [0402L_cap]  (hidden comment: 0402YC104JAT4A)
C66  value 0.1 uF  [0402L_cap]  (hidden comment: 0402YC104JAT4A)
C67  value 0.1 uF  [0402L_cap]  (hidden comment: 0402YC104JAT4A)
C68  value 0.1 uF  Voltage - Rated: 25V  [0402L_cap]  (hidden comment: GRT155R71E104KE01J)
C69  value 0.1 uF  Voltage - Rated: 25V  [0402L_cap]  (hidden comment: GRT155R71E104KE01J)
C70  value 0.1 uF  Voltage - Rated: 25V  [0402L_cap]  (hidden comment: GRT155R71E104KE01J)
C71  value 0.1 uF  Voltage - Rated: 25V  [0402L_cap]  (hidden comment: GRT155R71E104KE01J)
C72  value 0.1 uF  Voltage - Rated: 25V  [0402L_cap]  (hidden comment: GRT155R71E104KE01J)
C73  value 0.1 uF  Voltage - Rated: 25V  [0402L_cap]  (hidden comment: GRT155R71E104KE01J)
C74  value 0.1 uF  [0402L_cap]  (hidden comment: 0402YC104JAT4A)
C75  value 0.1 uF  [0402L_cap]  (hidden comment: 0402YC104JAT4A)
C76  value 0.1 uF  [0402L_cap]  (hidden comment: 0402YC104JAT4A)
C77  value 0.1 uF  [0402L_cap]  (hidden comment: 0402YC104JAT4A)
C78  value 0.1 uF  Voltage - Rated: 25V  [0402L_cap]  (hidden comment: GRT155R71E104KE01J)
C79  value 0.1 uF  [0402L_cap]  (hidden comment: 0402YC104JAT4A)
C80  value 0.1 uF  [0402L_cap]  (hidden comment: 0402YC104JAT4A)
C81  value 0.1 uF  [0402L_cap]  (hidden comment: 0402YC104JAT4A)
C82  value 0.1 uF  [0402L_cap]  (hidden comment: 0402YC104JAT4A)
C83  value 180 pF  Voltage - Rated: 50V  [0402L_cap]  (hidden comment: 04025C181KAT2A)
C84  value 270 pF  Voltage - Rated: 50V  [0402L_cap]  (hidden comment: 04025C271JAT2A)
C85  value 0.1 uF  [0402L_cap]  (hidden comment: 0402YC104JAT4A)
C86  value 0.1 uF  [0402L_cap]  (hidden comment: 0402YC104JAT4A)
C87  value 0.1 uF  [0402L_cap]  (hidden comment: 0402YC104JAT4A)
C88  value 0.1 uF  [0402L_cap]  (hidden comment: 0402YC104JAT4A)
C89  value 0.1 uF  Voltage - Rated: 25V  [0402L_cap]  (hidden comment: GRT155R71E104KE01J)
C90  value 0.1 uF  Voltage - Rated: 25V  [0402L_cap]  (hidden comment: GRT155R71E104KE01J)
C91  value 0.1 uF  Voltage - Rated: 25V  [0402L_cap]  (hidden comment: GRT155R71E104KE01J)
C92  value 0.1 uF  Voltage - Rated: 25V  [0402L_cap]  (hidden comment: GRT155R71E104KE01J)
C93  value 0.1 uF  Voltage - Rated: 25V  [0402L_cap]  (hidden comment: GRT155R71E104KE01J)
C94  value 0.1 uF  Voltage - Rated: 25V  [0402L_cap]  (hidden comment: GRT155R71E104KE01J)
J6  Text1: DCLKIN  [FP-132134-15_CONN_SMA_JACK-MFG]  (hidden comment: 132134-15)
J7  Text1: CLK  [FP-132134-15_CONN_SMA_JACK-MFG]  (hidden comment: 132134-15)
J8  Text1: INAp  [FP-132134-15_CONN_SMA_JACK-MFG]  (hidden comment: 132134-15)
J9  Text1: INAm  [FP-132134-15_CONN_SMA_JACK-MFG]  (hidden comment: 132134-15)
J10  Text1: INBp  [FP-132134-15_CONN_SMA_JACK-MFG]  (hidden comment: 132134-15)
J11  Text1: INBm  [FP-132134-15_CONN_SMA_JACK-MFG]  (hidden comment: 132134-15)
J12  Text1: SYNC  [FP-132134-15_CONN_SMA_JACK-MFG]  (hidden comment: 132134-15)
L2  value 82 nH  [TDK_IND_0402]  (hidden comment: MLG1005S82NJT000)
L3  value 330 nH  [TDK_IND_0402]  (hidden comment: MLG1005SR33JT000)
L4  value 82 nH  [TDK_IND_0402]  (hidden comment: MLG1005S82NJT000)
L5  value 330 nH  [TDK_IND_0402]  (hidden comment: MLG1005SR33JT000)
L6  value 82 nH  [TDK_IND_0402]  (hidden comment: MLG1005S82NJT000)
L7  value 330 nH  [TDK_IND_0402]  (hidden comment: MLG1005SR33JT000)
L8  value 82 nH  [TDK_IND_0402]  (hidden comment: MLG1005S82NJT000)
L9  value 330 nH  [TDK_IND_0402]  (hidden comment: MLG1005SR33JT000)
R81  value 1 kΩ  [0402L]  (hidden comment: ERA-2ARB102X)
R82  value 1 kΩ  [0402L]  (hidden comment: ERA-2ARB102X)
R83  value 0 Ω  [0402L]  (hidden comment: ERJ-2GE0R00X)
R84  value 49.9 Ω  [0402L]  (hidden comment: ERJ-2RKF49R9X)
R85  value 49.9 Ω  [0402L]  (hidden comment: ERJ-2RKF49R9X)
R86  value 1 kΩ  [0402L]  (hidden comment: ERA-2ARB102X)
R87  value 1 kΩ  [0402L]  (hidden comment: ERA-2ARB102X)
R88  value 499 Ω  [0402L]  (hidden comment: ERJ-2RKF4990X)
R89  value 0 Ω  [0402L]  (hidden comment: ERJ-2GE0R00X)
R90  value 0 Ω  [0402L]  (hidden comment: ERJ-2GE0R00X)
R91  value 0 Ω  [0402L]  (hidden comment: ERJ-2GE0R00X)
R92  value 1 kΩ  [0402L]  (hidden comment: ERA-2ARB102X)
R93  value 49.9 Ω  [0402L]  (hidden comment: ERJ-2RKF49R9X)
R94  value 200 Ω  [0402L]  (hidden comment: ERJ-2RKF2000X)
R95  value 37.4 Ω  [0402L]  (hidden comment: ERJ-2RKF37R4X)
R96  value 499 Ω  [0402L]  (hidden comment: ERJ-2RKF4990X)
R97  value 49.9 Ω  [0402L]  (hidden comment: ERJ-2RKF49R9X)
R98  value 0 Ω  [0402L]  (hidden comment: ERJ-2GE0R00X)
R99  value 200 Ω  [0402L]  (hidden comment: ERJ-2RKF2000X)
R100  value 37.4 Ω  [0402L]  (hidden comment: ERJ-2RKF37R4X)
R101  value 1 kΩ  [0402L]  (hidden comment: ERA-2ARB102X)
R102  value 0 Ω  [0402L]  (hidden comment: ERJ-2GE0R00X)
R103  value 0 Ω  [0402L]  (hidden comment: ERJ-2GE0R00X)
R104  value 0 Ω  [0402L]  (hidden comment: ERJ-2GE0R00X)
R105  value 10 kΩ  [0402L]  (hidden comment: ERJ-2GEJ103X)
R106  value 0 Ω  [0402L]  (hidden comment: ERJ-2GE0R00X)
R107  value 0 Ω  [0402L]  (hidden comment: ERJ-2GE0R00X)
R108  value 27 Ω  [0402L]  (hidden comment: ERJ-2RKF27R0X)
R109  value 27 Ω  [0402L]  (hidden comment: ERJ-2RKF27R0X)
R110  value 499 Ω  [0402L]  (hidden comment: ERJ-2RKF4990X)
R111  value 499 Ω  [0402L]  (hidden comment: ERJ-2RKF4990X)
R112  value 0 Ω  [0402L]  (hidden comment: ERJ-2GE0R00X)
R113  value 0 Ω  [0402L]  (hidden comment: ERJ-2GE0R00X)
R114  value 0 Ω  [0402L]  (hidden comment: ERJ-2GE0R00X)
R115  value 1 kΩ  [0402L]  (hidden comment: ERA-2ARB102X)
R116  value 49.9 Ω  [0402L]  (hidden comment: ERJ-2RKF49R9X)
R117  value 200 Ω  [0402L]  (hidden comment: ERJ-2RKF2000X)
R118  value 37.4 Ω  [0402L]  (hidden comment: ERJ-2RKF37R4X)
R119  value 49.9 Ω  [0402L]  (hidden comment: ERJ-2RKF49R9X)
R120  value 1 kΩ  [0402L]  (hidden comment: ERA-2ARB102X)
R121  value 499 Ω  [0402L]  (hidden comment: ERJ-2RKF4990X)
R122  value 0 Ω  [0402L]  (hidden comment: ERJ-2GE0R00X)
R123  value 200 Ω  [0402L]  (hidden comment: ERJ-2RKF2000X)
R124  value 37.4 Ω  [0402L]  (hidden comment: ERJ-2RKF37R4X)
R125  value 0 Ω  [0402L]  (hidden comment: ERJ-2GE0R00X)
R126  value 0 Ω  [0402L]  (hidden comment: ERJ-2GE0R00X)
R127  value 0 Ω  [0402L]  (hidden comment: ERJ-2GE0R00X)
R128  value 10 kΩ  [0402L]  (hidden comment: ERJ-2GEJ103X)
R129  value 0 Ω  [0402L]  (hidden comment: ERJ-2GE0R00X)
R130  value 0 Ω  [0402L]  (hidden comment: ERJ-2GE0R00X)
R131  value 27 Ω  [0402L]  (hidden comment: ERJ-2RKF27R0X)
R132  value 27 Ω  [0402L]  (hidden comment: ERJ-2RKF27R0X)
R133  value 499 Ω  [0402L]  (hidden comment: ERJ-2RKF4990X)
R140  value 0 Ω  [0402L]  (hidden comment: ERJ-2GE0R00X)
R141  value 49.9 Ω  [0402L]  (hidden comment: ERJ-2RKF49R9X)
T1  ADT2-1T+  [FP-ADT2-1T+_SMD6-MFG]
T2  ADT2-1T+  [FP-ADT2-1T+_SMD6-MFG]
T3  ADT2-1T+  [FP-ADT2-1T+_SMD6-MFG]
T4  ADT2-1T+  [FP-ADT2-1T+_SMD6-MFG]
TP9  Text1: VSA-  [Keystone5129]  (hidden comment: 5129)
TP10  Text1: VSA+  [Keystone5010]  (hidden comment: 5010)
TP11  Text1: VSB-  [Keystone5129]  (hidden comment: 5129)
TP12  Text1: VSB+  [Keystone5010]  (hidden comment: 5010)
U14  THS4541IRGTR  [RGT0016A_NV]
U15  THS4541IRGTR  [RGT0016A_NV]

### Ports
AMP_INAM (in, see 3), AMP_INAP (in, see 3), AMP_INBM (in, see 3), AMP_INBP (in, see 3), AMP_OUT_AM (out, see 3), AMP_OUT_AP (out, see 3), AMP_OUT_BM (out, see 3), AMP_OUT_BP (out, see 3), CLK (in, see 4), D00 (in, see 4, 6), DCLKIN (in, see 4), FMC_DCLKIN (in, see 6), INAM (in, see 4), INAP (in, see 4), INBM (in, see 4), INBP (in, see 4)

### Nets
AVDD: R81.2 R82.2
FDA_3V3: R98.1 R102.2 R122.1 R126.2
GND: C55.1 C57.1 C58.1 C60.2 C63.2 C64.1 C68.1 C69.1 C70.1 C71.1 C72.1 C73.1 C77.1 C78.1 C79.1 C80.2 C82.2 C86.1 C89.1 C90.1 C91.1 C92.1 C93.1 C94.1 J6.2 J6.3 J6.4 J6.5 J7.2 J7.3 J7.4 J7.5 J8.2 J8.3 J8.4 J8.5 J9.2 J9.3 J9.4 J9.5 J10.2 J10.3 J10.4 J10.5 J11.2 J11.3 J11.4 J11.5 J12.2 J12.3 J12.4 J12.5 R84.1 R85.1 R86.1 R87.1 R105.1 R106.1 R128.1 R129.1 R141.1 T1.1(PRIMARY) T3.1(PRIMARY) U14.17(EP) U15.17(EP)
VCM: C55.2 C60.1 C78.2 C80.1 R92.1 R101.2 R115.1 R120.2 U14.9(VOCM) U15.9(VOCM)
AMP_INAM: C53.2 R99.1 R108.2 ; port AMP_INAM
AMP_INAP: C66.1 R94.1 R109.2 ; port AMP_INAP
AMP_INBM: C74.2 R123.1 R131.2 ; port AMP_INBM
AMP_INBP: C88.1 R117.1 R132.2 ; port AMP_INBP
AMP_OUT_AM: C62.1 L5.2 R89.2 R96.1 ; port AMP_OUT_AM
AMP_OUT_AP: C62.2 L3.2 R96.2 R104.2 ; port AMP_OUT_AP
AMP_OUT_BM: C84.1 L9.2 R112.2 R121.1 ; port AMP_OUT_BM
AMP_OUT_BP: C84.2 L7.2 R121.2 R127.1 ; port AMP_OUT_BP
CLK: C52.1 R82.1 R87.2 ; port CLK
D00: R140.2 ; port D00
DCLKIN: C51.1 R81.1 R86.2 ; port DCLKIN
FMC_DCLKIN: R83.2 ; port FMC_DCLKIN
INAM: C63.1 R103.2 ; port INAM
INAP: C57.2 R91.2 ; port INAP
INBM: C82.1 R125.2 ; port INBM
INBP: C77.2 R114.2 ; port INBP
NetC51_2: C51.2 J6.1 R83.1 R84.2
NetC52_2: C52.2 J7.1 R85.2
NetC53_1: C53.1 C59.1 J8.1 R90.1
NetC54_1: C54.1 R90.2
NetC54_2: C54.2 C56.2 R89.1 R91.1 R92.2
NetC56_1: C56.1 R93.2 T2.3(PRIMARY_DOT)
NetC58_2: C58.2 R93.1 R97.2
NetC59_2: C59.2 T1.3(PRIMARY_DOT)
NetC61_1: C61.1 L4.2 L5.1
NetC61_2: C61.2 L2.2 L3.1
NetC64_2: C64.2 T1.5(SECONDARY_CT) T2.5(SECONDARY_CT)
NetC65_1: C65.1 R97.1 T2.1(PRIMARY)
NetC65_2: C65.2 C67.2 R101.1 R103.1 R104.1
NetC66_2: C66.2 J9.1 R107.1
NetC67_1: C67.1 R107.2
NetC68_2: C68.2 R108.1
NetC69_2: C69.2 R109.1
NetC70_2: C70.2 C71.2 C72.2 C73.2 R102.1 TP10.1 U14.5(VS+) U14.6(VS+) U14.7(VS+) U14.8(VS+)
NetC74_1: C74.1 C81.1 J10.1 R113.1
NetC75_1: C75.1 R113.2
NetC75_2: C75.2 C76.2 R112.1 R114.1 R115.2
NetC76_1: C76.1 R116.2 T4.3(PRIMARY_DOT)
NetC79_2: C79.2 R116.1 R119.2
NetC81_2: C81.2 T3.3(PRIMARY_DOT)
NetC83_1: C83.1 L8.2 L9.1
NetC83_2: C83.2 L6.2 L7.1
NetC85_1: C85.1 R119.1 T4.1(PRIMARY)
NetC85_2: C85.2 C87.2 R120.1 R125.1 R127.2
NetC86_2: C86.2 T3.5(SECONDARY_CT) T4.5(SECONDARY_CT)
NetC87_1: C87.1 R130.2
NetC88_2: C88.2 J11.1 R130.1
NetC89_2: C89.2 R131.1
NetC90_2: C90.2 R132.1
NetC91_2: C91.2 C92.2 C93.2 C94.2 R126.1 TP12.1 U15.5(VS+) U15.6(VS+) U15.7(VS+) U15.8(VS+)
NetJ12_1: J12.1 R140.1 R141.2
NetL2_1: L2.1 R95.2
NetL4_1: L4.1 R100.2
NetL6_1: L6.1 R118.2
NetL8_1: L8.1 R124.2
NetR88_1: R88.1 R94.2 U14.2(IN+)
NetR88_2: R88.2 U14.1(FB-)
NetR95_1: R95.1 U14.11(OUT-)
NetR98_2: R98.2 R105.2 U14.12(~{PD})
NetR99_2: R99.2 R110.1 U14.3(IN-)
NetR100_1: R100.1 U14.10(OUT+)
NetR106_2: R106.2 TP9.1 U14.13(VS-) U14.14(VS-) U14.15(VS-) U14.16(VS-)
NetR110_2: R110.2 U14.4(FB+)
NetR111_1: R111.1 U15.1(FB-)
NetR111_2: R111.2 R117.2 U15.2(IN+)
NetR118_1: R118.1 U15.11(OUT-)
NetR122_2: R122.2 R128.2 U15.12(~{PD})
NetR123_2: R123.2 R133.2 U15.3(IN-)
NetR124_1: R124.1 U15.10(OUT+)
NetR129_2: R129.2 TP11.1 U15.13(VS-) U15.14(VS-) U15.15(VS-) U15.16(VS-)
NetR133_1: R133.1 U15.4(FB+)
NetT1_4: T1.4(SECONDARY) T2.6(SECONDARY_DOT)
NetT1_6: T1.6(SECONDARY_DOT) T2.4(SECONDARY)
NetT3_4: T3.4(SECONDARY) T4.6(SECONDARY_DOT)
NetT3_6: T3.6(SECONDARY_DOT) T4.4(SECONDARY)

Not connected (* = marked no-connect by the designer): T1 2(NC)*; T2 2(NC)*; T3 2(NC)*; T4 2(NC)*

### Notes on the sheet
- Analog Input Default:
- AC coupled
- Balun
- Alternate Input Config option w/FDA
- 20-MHz LPF
- DEFAULT PULL LOW - OFF
- (near C68) DC-coupled- change C's to zero ohm
- AC/DC coupling config
- (near C68) AC-coupled - keep C as 0.1uF
- C

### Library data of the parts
C51 C52 C55 C68-C73 C78 C89-C94 = capcc09401: CAP CER 0.1UF 25V X7R 0402; Manufacturer: Murata; CompType: Capacitor Ceramic; Tolerance: ±10%; SizeX_mm: 1; SizeY_mm: 0.5; SizeZ_mm: 0.7
C53 C54 C56-C60 C63-C67 C74-C77 C79-C82 C85-C88 = capcc01284: CAP CER 0.1UF 16V X7R 0402; Manufacturer: KYOCERA AVX; SizeZ_mm: 0.56; Tolerance: ±5%; SizeX_mm: 1; SizeY_mm: 0.5; CompType: Capacitor Ceramic
C61 C83 = capcc06444: CAP CER 180PF 50V X7R 0402; Manufacturer: KYOCERA AVX; CompType: Capacitor Ceramic; Tolerance: ±10%; SizeX_mm: 1; SizeY_mm: 0.5; SizeZ_mm: 0.56
C62 C84 = capcc00002: CAP CER 270PF 50V X7R 0402; Manufacturer: KYOCERA AVX; CompType: Capacitor Ceramic; Tolerance: ±5%; SizeX_mm: 1; SizeY_mm: 0.5; SizeZ_mm: 0.56
J6-J12 = cmp00028: SMA Connector Jack, Female Socket 50Ohm Surface Mount, Through Hole Solder; Manufacturer: Amphenol RF; CompType: RF Connector
L2 L4 L6 L8 = indrf00701: FIXED IND 82NH 200MA 1.6 OHM SMD; Manufacturer: TDK Corporation; CompType: Inductor RF; Material: Ceramic, Non-Magnetic; Tolerance: ±5%; DC Resistance (DCR): 1.6 Ω; Q @ Freq: 8 @ 100MHz; Frequency - Self Resonant: 700 MHz; SizeX_mm: 1; SizeY_mm: 0.5; SizeZ_mm: 0.55
L3 L5 L7 L9 = indrf00703: FIXED IND 330NH 50MA 7 OHM SMD; Manufacturer: TDK Corporation; CompType: Inductor RF; Material: Ceramic, Non-Magnetic; Tolerance: ±5%; DC Resistance (DCR): 7 Ω; Frequency - Self Resonant: 350 MHz; SizeX_mm: 1; SizeY_mm: 0.5; SizeZ_mm: 0.55
R81 R86 = RSMD040200016: RES SMD 1K OHM 0.1% 1/16W 0402; Manufacturer: Panasonic Electronic Components; CompType: Resistor SMD; Power (Watts): 0.063W, 1/16W; Temperature Coefficient: ±10ppm/°C; SizeX_mm: 1; SizeY_mm: 0.5; SizeZ_mm: 0.4
R82 R87 R92 R101 R115 R120 = RSMD040200016: RES SMD 1K OHM 0.1% 1/16W 0402; Manufacturer: Panasonic Electronic Components; Power (Watts): 0.063W, 1/16W; Temperature Coefficient: ±10ppm/°C; SizeX_mm: 1; SizeY_mm: 0.5; SizeZ_mm: 0.4; CompType: Resistor SMD
R83 R89 R91 R98 R102-R104 R106 R122 R126 R129 R140 = RSMD040200001: RES SMD 0 OHM JUMPER 1/10W 0402; Manufacturer: Panasonic Electronic Components; CompType: Resistor SMD; Power (Watts): 0.1W, 1/10W; SizeX_mm: 1; SizeY_mm: 0.5; SizeZ_mm: 0.4
R84 R85 R93 R97 R116 R119 R141 = RSMD040202911: RES SMD 49.9 OHM 1% 1/10W 0402; Manufacturer: Panasonic Electronic Components; CompType: Resistor SMD; Power (Watts): 0.1W, 1/10W; Temperature Coefficient: ±100ppm/°C; SizeX_mm: 1; SizeY_mm: 0.5; SizeZ_mm: 0.4
R88 R96 R110 R111 R121 R133 = RSMD040202923: RES SMD 499 OHM 1% 1/10W 0402; Manufacturer: Panasonic Electronic Components; CompType: Resistor SMD; Power (Watts): 0.1W, 1/10W; Temperature Coefficient: ±100ppm/°C; SizeX_mm: 1; SizeY_mm: 0.5; SizeZ_mm: 0.4
R90 R107 R112-R114 R125 R127 R130 = RSMD040200001: RES SMD 0 OHM JUMPER 1/10W 0402; Manufacturer: Panasonic Electronic Components; Power (Watts): 0.1W, 1/10W; SizeX_mm: 1; SizeY_mm: 0.5; SizeZ_mm: 0.4; CompType: Resistor SMD
R94 R99 R117 R123 = RSMD040201387: RES SMD 200 OHM 1% 1/10W 0402; Manufacturer: Panasonic Electronic Components; CompType: Resistor SMD; Power (Watts): 0.1W, 1/10W; Temperature Coefficient: ±100ppm/°C; SizeX_mm: 1; SizeY_mm: 0.5; SizeZ_mm: 0.4
R95 R100 R118 R124 = RSMD040202422: RES SMD 37.4 OHM 1% 1/10W 0402; Manufacturer: Panasonic Electronic Components; CompType: Resistor SMD; Power (Watts): 0.1W, 1/10W; Temperature Coefficient: ±100ppm/°C; SizeX_mm: 1; SizeY_mm: 0.5; SizeZ_mm: 0.4
R105 R128 = RSMD040200306: RES SMD 10K OHM 5% 1/10W 0402; Manufacturer: Panasonic Electronic Components; CompType: Resistor SMD; Power (Watts): 0.1W, 1/10W; Temperature Coefficient: ±200ppm/°C; SizeX_mm: 1; SizeY_mm: 0.5; SizeZ_mm: 0.4
R108 R109 R131 R132 = RSMD040201785: RES SMD 27 OHM 1% 1/10W 0402; Manufacturer: Panasonic Electronic Components; CompType: Resistor SMD; Power (Watts): 0.1W, 1/10W; Temperature Coefficient: ±100ppm/°C; SizeX_mm: 1; SizeY_mm: 0.5; SizeZ_mm: 0.4
T1-T4 = CMP-0089317-2: RF Transformer Surface Mount 50Ω 4.5 to 3000 MHz; Manufacturer: Mini-Circuits; Return Loss: 7.38dB; SizeZ_mm: 2.84mm; Insertion Loss: 0.3-1.25dB; AEC Qualified: No; Frequency_Fixed: 0.4-450MHz; Ns1toNp: 2:1:1; DCR_ohm: 2
TP9 TP11 = cmp00049: Test Point, Multipurpose, Purple, TH; Manufacturer: Keystone
TP10 TP12 = cmp00040: Test Point, Multipurpose, Red, TH; Manufacturer: Keystone
U14 U15 = CMP-0065559-3: High-Speed Differential I/O Amplifier, RGT0016A (VQFN-16); Alternate PartNumber: THS4541IRGTT; Manufacturer: Texas Instruments; SizeZ_mm: 4; SizeArea_mm2: 16; CompType: IC; SizeAreaWB_mm2: 25; AEC Category: Q200; AEC Qualified: N

## Sheet ADC3910D125EVM_DUT_RevE2.SchDoc
size 431 x 279 mm; Date: Not shown in title block; ApprovedBy: Not shown in title block; CheckedBy: Not shown in title block; Author: Not shown in title block; CompanyName: Not shown in title block; Engineer: Not shown in title block; Organization: Not shown in title block; Address1: Not shown in title block; Address2: Not shown in title block; Address3: Not shown in title block; Address4: Not shown in title block; DocumentNumber: 2; Revision: Use project parameter SCH_Rev; SheetNumber: 4; SheetTotal: 7; PageSetup: Record=PageOptions¦CenterHorizontal=True¦CenterVertical=True¦PrintScale=1.00¦XCorrection=1.00¦YCorrection=1.00¦PrintKind=0¦BorderSize=5000000¦LeftOffset=0¦BottomOffset=0¦Orientation=2¦PaperLength=1000¦PaperWidth=1000¦Scale=100¦PaperSource=15¦PrintQuality=600¦MediaType=1¦DitherType=10¦PaperKind=Letter¦PrintScaleMode=1
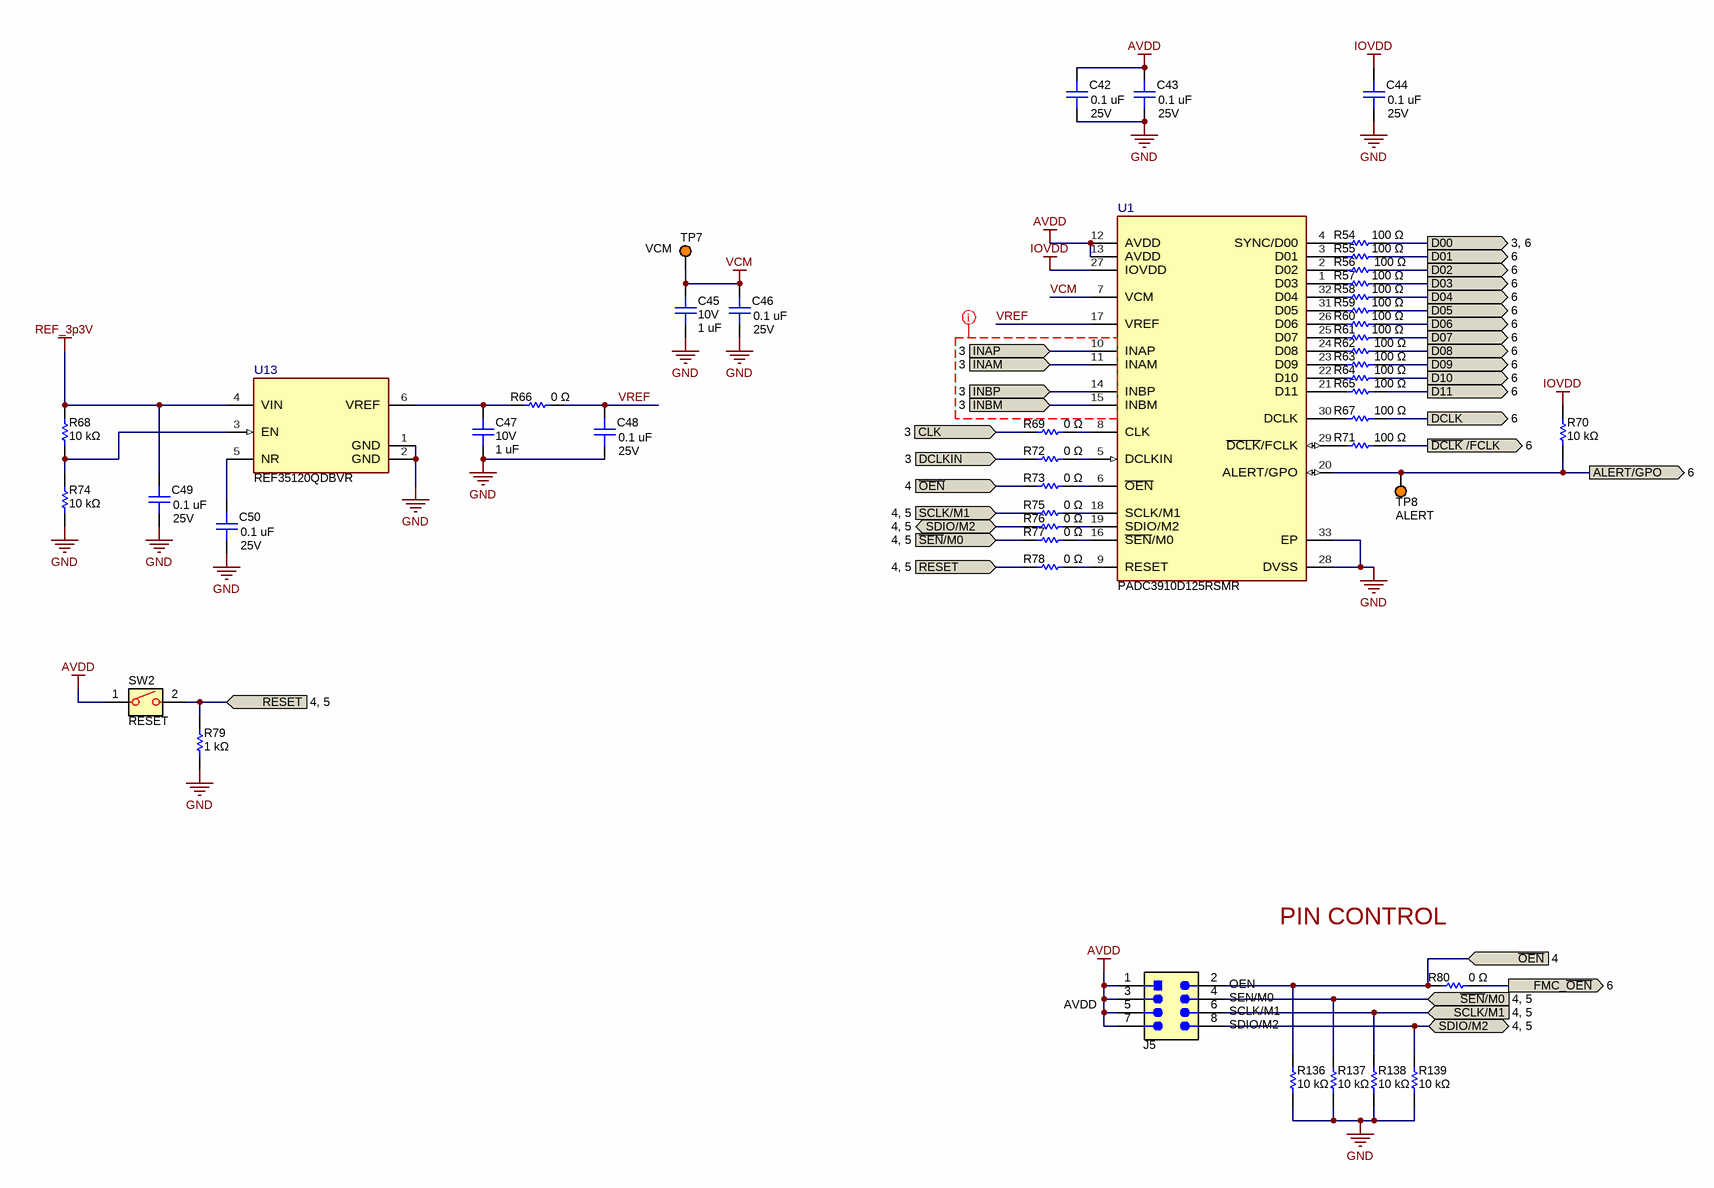
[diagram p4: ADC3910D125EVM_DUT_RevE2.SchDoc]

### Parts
C42  value 0.1 uF  Voltage - Rated: 25V  [0402L_cap]  (hidden comment: GRT155R71E104KE01J)
C43  value 0.1 uF  Voltage - Rated: 25V  [0402L_cap]  (hidden comment: GRT155R71E104KE01J)
C44  value 0.1 uF  Voltage - Rated: 25V  [0402L_cap]  (hidden comment: GRT155R71E104KE01J)
C45  value 1 uF  Voltage - Rated: 10V  [0402L_cap]  (hidden comment: 0402ZD105KAT2A)
C46  value 0.1 uF  Voltage - Rated: 25V  [0402L_cap]  (hidden comment: GRT155R71E104KE01J)
C47  value 1 uF  Voltage - Rated: 10V  [0402L_cap]  (hidden comment: 0402ZD105KAT2A)
C48  value 0.1 uF  Voltage - Rated: 25V  [0402L_cap]  (hidden comment: GRT155R71E104KE01J)
C49  value 0.1 uF  Voltage - Rated: 25V  [0402L_cap]  (hidden comment: GRT155R71E104KE01J)
C50  value 0.1 uF  Voltage - Rated: 25V  [0402L_cap]  (hidden comment: GRT155R71E104KE01J)
J5  Text8: SDIO/M2  Text4: SEN/M0  Text6: SCLK/M1  Text1: AVDD  Text2: OEN  [PBC04DAAN]  (hidden comment: PBC04DAAN)
R54  value 100 Ω  [0402L]  (hidden comment: ERJ-2RKF1000X)
R55  value 100 Ω  [0402L]  (hidden comment: ERJ-2RKF1000X)
R56  value 100 Ω  [0402L]  (hidden comment: ERJ-2RKF1000X)
R57  value 100 Ω  [0402L]  (hidden comment: ERJ-2RKF1000X)
R58  value 100 Ω  [0402L]  (hidden comment: ERJ-2RKF1000X)
R59  value 100 Ω  [0402L]  (hidden comment: ERJ-2RKF1000X)
R60  value 100 Ω  [0402L]  (hidden comment: ERJ-2RKF1000X)
R61  value 100 Ω  [0402L]  (hidden comment: ERJ-2RKF1000X)
R62  value 100 Ω  [0402L]  (hidden comment: ERJ-2RKF1000X)
R63  value 100 Ω  [0402L]  (hidden comment: ERJ-2RKF1000X)
R64  value 100 Ω  [0402L]  (hidden comment: ERJ-2RKF1000X)
R65  value 100 Ω  [0402L]  (hidden comment: ERJ-2RKF1000X)
R66  value 0 Ω  [0402L]  (hidden comment: ERJ-2GE0R00X)
R67  value 100 Ω  [0402L]  (hidden comment: ERJ-2RKF1000X)
R68  value 10 kΩ  [0402L]  (hidden comment: ERJ-2RKF1002X)
R69  value 0 Ω  [0402L]  (hidden comment: ERJ-2GE0R00X)
R70  value 10 kΩ  [0402L]  (hidden comment: ERJ-2RKF1002X)
R71  value 100 Ω  [0402L]  (hidden comment: ERJ-2RKF1000X)
R72  value 0 Ω  [0402L]  (hidden comment: ERJ-2GE0R00X)
R73  value 0 Ω  [0402L]  (hidden comment: ERJ-2GE0R00X)
R74  value 10 kΩ  [0402L]  (hidden comment: ERJ-2RKF1002X)
R75  value 0 Ω  [0402L]  (hidden comment: ERJ-2GE0R00X)
R76  value 0 Ω  [0402L]  (hidden comment: ERJ-2GE0R00X)
R77  value 0 Ω  [0402L]  (hidden comment: ERJ-2GE0R00X)
R78  value 0 Ω  [0402L]  (hidden comment: ERJ-2GE0R00X)
R79  value 1 kΩ  [0402L]  (hidden comment: ERJ-2RKF1001X)
R80  value 0 Ω  [0402L]  (hidden comment: ERJ-2GE0R00X)
R136  value 10 kΩ  [0402L]  (hidden comment: ERJ-2RKF1002X)
R137  value 10 kΩ  [0402L]  (hidden comment: ERJ-2RKF1002X)
R138  value 10 kΩ  [0402L]  (hidden comment: ERJ-2RKF1002X)
R139  value 10 kΩ  [0402L]  (hidden comment: ERJ-2RKF1002X)
SW2  Text1: RESET  [FSMSM]  (hidden comment: FSMSM)
TP7  Text1: VCM  [Keystone5013]  (hidden comment: 5013)
TP8  Text1: ALERT  [Keystone5013]  (hidden comment: 5013)
U1  PartNumber: PADC3910D125RSMR  [RSN0032B-MFG]  (hidden comment: PADC392S125RSNR)
U13  REF35120QDBVR  [DBV0006A-MFG]

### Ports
ALERT/GPO (out, see 6), CLK (in, see 3), D00 (out, see 3, 6), D01 (out, see 6), D02 (out, see 6), D03 (out, see 6), D04 (out, see 6), D05 (out, see 6), D06 (out, see 6), D07 (out, see 6), D08 (out, see 6), D09 (out, see 6), D10 (out, see 6), D11 (out, see 6), DCLK (out, see 6), DCLKIN (in, see 3), FMC_~{OEN} (out, see 6), INAM (in, see 3), INAP (in, see 3), INBM (in, see 3), INBP (in, see 3), RESET (in, see 4, 5), SCLK/M1 (in, see 4, 5), SDIO/M2 (bidir, see 4, 5), ~{DCLK} /FCLK (out, see 6), ~{OEN} (in, see 4), ~{SEN}/M0 (in, see 4, 5)

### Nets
AVDD: C42.2 C43.2 J5.1 J5.3 J5.5 J5.7 SW2.1 U1.12(AVDD) U1.13(AVDD)
GND: C42.1 C43.1 C44.1 C45.1 C46.1 C47.1 C48.1 C49.1 C50.1 R74.1 R79.1 R136.1 R137.1 R138.1 R139.1 U1.28(DVSS) U1.33(EP) U13.1(GND) U13.2(GND)
IOVDD: C44.2 R70.2 U1.27(IOVDD)
REF_3p3V: C49.2 R68.2 U13.4(VIN)
VCM: C45.2 C46.2 TP7.1 U1.7(VCM)
ALERT/GPO: R70.1 TP8.1 U1.20(ALERT/GPO) ; port ALERT/GPO
CLK: R69.1 ; port CLK
D00: R54.2 ; port D00
D01: R55.2 ; port D01
D02: R56.2 ; port D02
D03: R57.2 ; port D03
D04: R58.2 ; port D04
D05: R59.2 ; port D05
D06: R60.2 ; port D06
D07: R61.2 ; port D07
D08: R62.2 ; port D08
D09: R63.2 ; port D09
D10: R64.2 ; port D10
D11: R65.2 ; port D11
~{DCLK} /FCLK: R71.2 ; port ~{DCLK} /FCLK
DCLK: R67.2 ; port DCLK
DCLKIN: R72.1 ; port DCLKIN
FMC_~{OEN}: R80.2 ; port FMC_~{OEN}
INAM: U1.11(INAM) ; port INAM
INAP: U1.10(INAP) ; port INAP
INBM: U1.15(INBM) ; port INBM
INBP: U1.14(INBP) ; port INBP
~{OEN}: J5.2 R73.1 R80.1 R136.2 ; port ~{OEN}
RESET: R78.1 R79.2 SW2.2 ; port RESET
~{SEN}/M0: J5.4 R77.1 R137.2 ; port ~{SEN}/M0
SCLK/M1: J5.6 R75.1 R138.2 ; port SCLK/M1
SDIO/M2: J5.8 R76.1 R139.2 ; port SDIO/M2
VREF: C48.2 R66.2 U1.17(VREF)
NetC47_2: C47.2 R66.1 U13.6(VREF)
NetC50_2: C50.2 U13.5(NR)
NetR54_1: R54.1 U1.4(SYNC/D00)
NetR55_1: R55.1 U1.3(D01)
NetR56_1: R56.1 U1.2(D02)
NetR57_1: R57.1 U1.1(D03)
NetR58_1: R58.1 U1.32(D04)
NetR59_1: R59.1 U1.31(D05)
NetR60_1: R60.1 U1.26(D06)
NetR61_1: R61.1 U1.25(D07)
NetR62_1: R62.1 U1.24(D08)
NetR63_1: R63.1 U1.23(D09)
NetR64_1: R64.1 U1.22(D10)
NetR65_1: R65.1 U1.21(D11)
NetR67_1: R67.1 U1.30(DCLK)
NetR68_1: R68.1 R74.2 U13.3(EN)
NetR69_2: R69.2 U1.8(CLK)
NetR71_1: R71.1 U1.29(~{DCLK}/FCLK)
NetR72_2: R72.2 U1.5(DCLKIN)
NetR73_2: R73.2 U1.6(~{OEN})
NetR75_2: R75.2 U1.18(SCLK/M1)
NetR76_2: R76.2 U1.19(SDIO/M2)
NetR77_2: R77.2 U1.16(~{SEN}/M0)
NetR78_2: R78.2 U1.9(RESET)

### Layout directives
net class Diff Input: (no net found under the mark)

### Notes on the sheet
- PIN CONTROL

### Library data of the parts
C42-C44 C46 C48-C50 = capcc09401: as C9 on sheet ADC3910D125EVM_Power_RevE2
C45 C47 = capcc02820: CAP CER 1UF 10V X5R 0402; Manufacturer: KYOCERA AVX; CompType: Capacitor Ceramic; Tolerance: ±10%; SizeX_mm: 1; SizeY_mm: 0.5; SizeZ_mm: 0.56
J5 = cmp00354: Header, 100mil, 4x2, Gold, TH; Manufacturer: Sullins Connector Solutions
R54-R65 R67 R71 = RSMD040200375: RES SMD 100 OHM 1% 1/10W 0402; Manufacturer: Panasonic Electronic Components; SizeX_mm: 1; SizeY_mm: 0.5; SizeZ_mm: 0.4; CompType: Resistor SMD; Power (Watts): 0.1W, 1/10W; Temperature Coefficient: ±100ppm/°C
R66 R69 R72 R73 R75-R78 R80 = RSMD040200001: as R83 on sheet ADC3910D125EVM_AIN_CLK_RevE2
R68 R70 R74 R136-R139 = RSMD040200314: as R32 on sheet ADC3910D125EVM_Power_RevE2
R79 = RSMD040200006: RES SMD 1K OHM 1% 1/10W 0402; Manufacturer: Panasonic Electronic Components; CompType: Resistor SMD; Power (Watts): 0.1W, 1/10W; Temperature Coefficient: ±100ppm/°C; SizeX_mm: 1; SizeY_mm: 0.5; SizeZ_mm: 0.4
SW2 = cmp00234: SWITCH TACTILE SPST-NO 0.05A 24V; Manufacturer: TE Connectivity; CompType: Push Button
TP7 TP8 = cmp00043: Test Point, Multipurpose, Orange, TH; Manufacturer: Keystone
U1 = CMP-0095180-2: Manufacturer: Texas Instruments; Standoff Height: 0mm; AEC Category: Q200; SizeZ_mm: 0.8mm; CompType: IC
U13 = CMP-0097703-1: Ultra Low-Power, High-Precision Voltage Reference; Manufacturer: Texas Instruments; Output Voltage: 1.2V; Standoff Height: 0mm; Output Type: Fixed; SizeZ_mm: 1.45mm; TaMax_C: +125°C; Min Supply Voltage: 1.45V; Number Of Outputs: 1; Reference Type: Series; TaMin_C: -55°C; Max Supply Voltage: 6V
